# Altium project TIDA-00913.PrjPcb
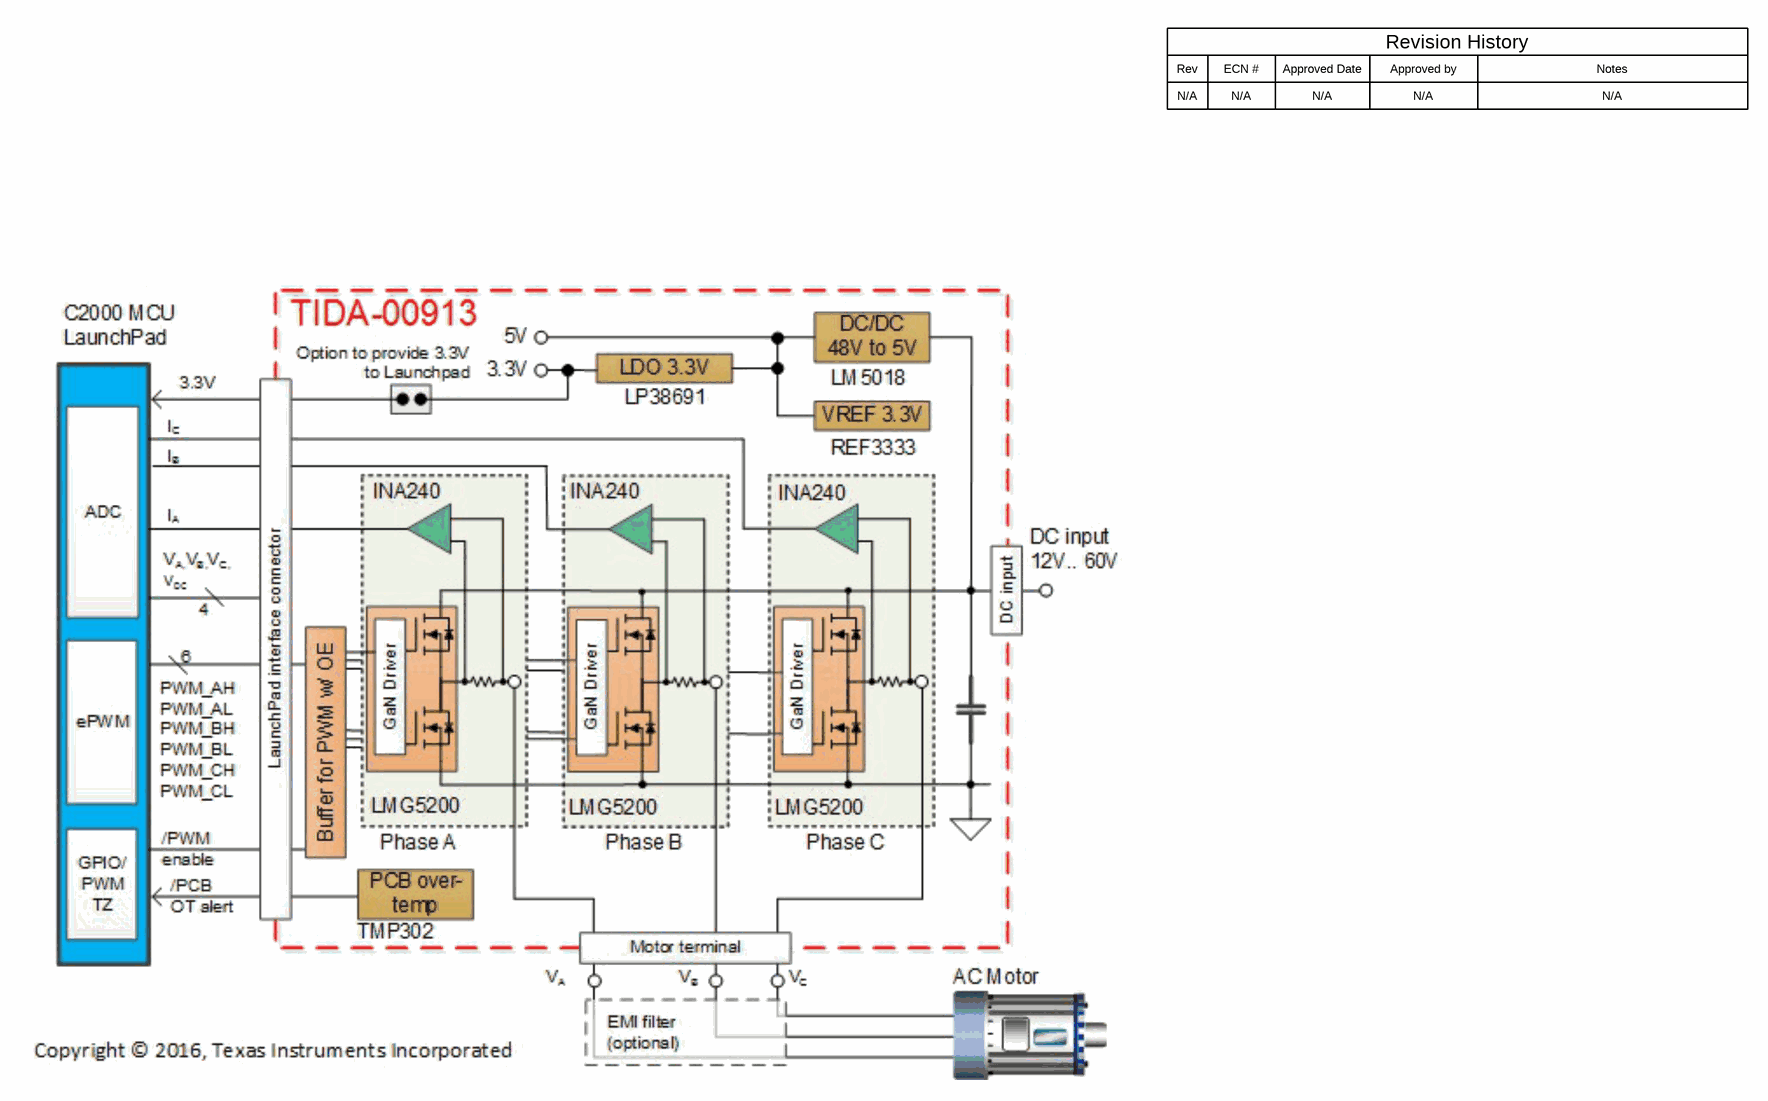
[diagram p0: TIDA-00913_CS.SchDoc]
TID: TIDA-00913; TechSupport: http://www.ti.com/support; SCH_Rev: E1; PRJ_Title: TI Design; PRJ_Number: TIDA-00913; PRJ_Engineer: Zhou/Staebler; PRJ_Customer: Public Release; PCB_Rev: E1; PCB_Layout: Zhou; CopyrightYear: 2016
6 sheets, 182 parts. Net scope: global (net labels, ports and power ports of the same name join across sheets).
Board file: TIDA-00913.PcbDoc
Sheets:
  TIDA-00913_CS.SchDoc
  TIDA-00913_GAN.SchDoc
  TIDA-00913_HW.SchDoc
  TIDA-00913_Interface.SchDoc
  TIDA-00913_PS.SchDoc
  TIDA-00913_Sensing.SchDoc

## Sheet TIDA-00913_CS.SchDoc
size 431 x 279 mm; Date: Not shown in title block; ApprovedBy: Not shown in title block; CheckedBy: Not shown in title block; Author: Not shown in title block; CompanyName: Not shown in title block; Engineer: Not shown in title block; Organization: Not shown in title block; Address1: Not shown in title block; Address2: Not shown in title block; Address3: Not shown in title block; Address4: Not shown in title block; DocumentNumber: 1; Revision: Use project parameter SCH_Rev; SheetNumber: 1; SheetTotal: 3; PageSetup: Record=PageOptions¦CenterHorizontal=True¦CenterVertical=True¦PrintScale=1.00¦XCorrection=1.00¦YCorrection=1.00¦PrintKind=0¦BorderSize=5000000¦LeftOffset=0¦BottomOffset=0¦Orientation=2¦PaperLength=1000¦PaperWidth=1000¦Scale=100¦PaperSource=15¦PrintQuality=600¦MediaType=1¦DitherType=10¦PaperKind=Letter¦PrintScaleMode=1

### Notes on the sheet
- Rev
- N/A
- ECN #
- Approved Date
- Approved by
- Revision History
- Notes

## Sheet TIDA-00913_GAN.SchDoc
size 431 x 279 mm; Date: Not shown in title block; ApprovedBy: Not shown in title block; CheckedBy: Not shown in title block; Author: Not shown in title block; CompanyName: Not shown in title block; Engineer: Not shown in title block; Organization: Not shown in title block; Address1: Not shown in title block; Address2: Not shown in title block; Address3: Not shown in title block; Address4: Not shown in title block; DocumentNumber: 1; Revision: Use project parameter SCH_Rev; SheetNumber: 2; SheetTotal: 3; PageSetup: Record=PageOptions¦CenterHorizontal=True¦CenterVertical=True¦PrintScale=1.00¦XCorrection=1.00¦YCorrection=1.00¦PrintKind=0¦BorderSize=5000000¦LeftOffset=0¦BottomOffset=0¦Orientation=2¦PaperLength=1000¦PaperWidth=1000¦Scale=100¦PaperSource=15¦PrintQuality=600¦MediaType=1¦DitherType=10¦PaperKind=Letter¦PrintScaleMode=1
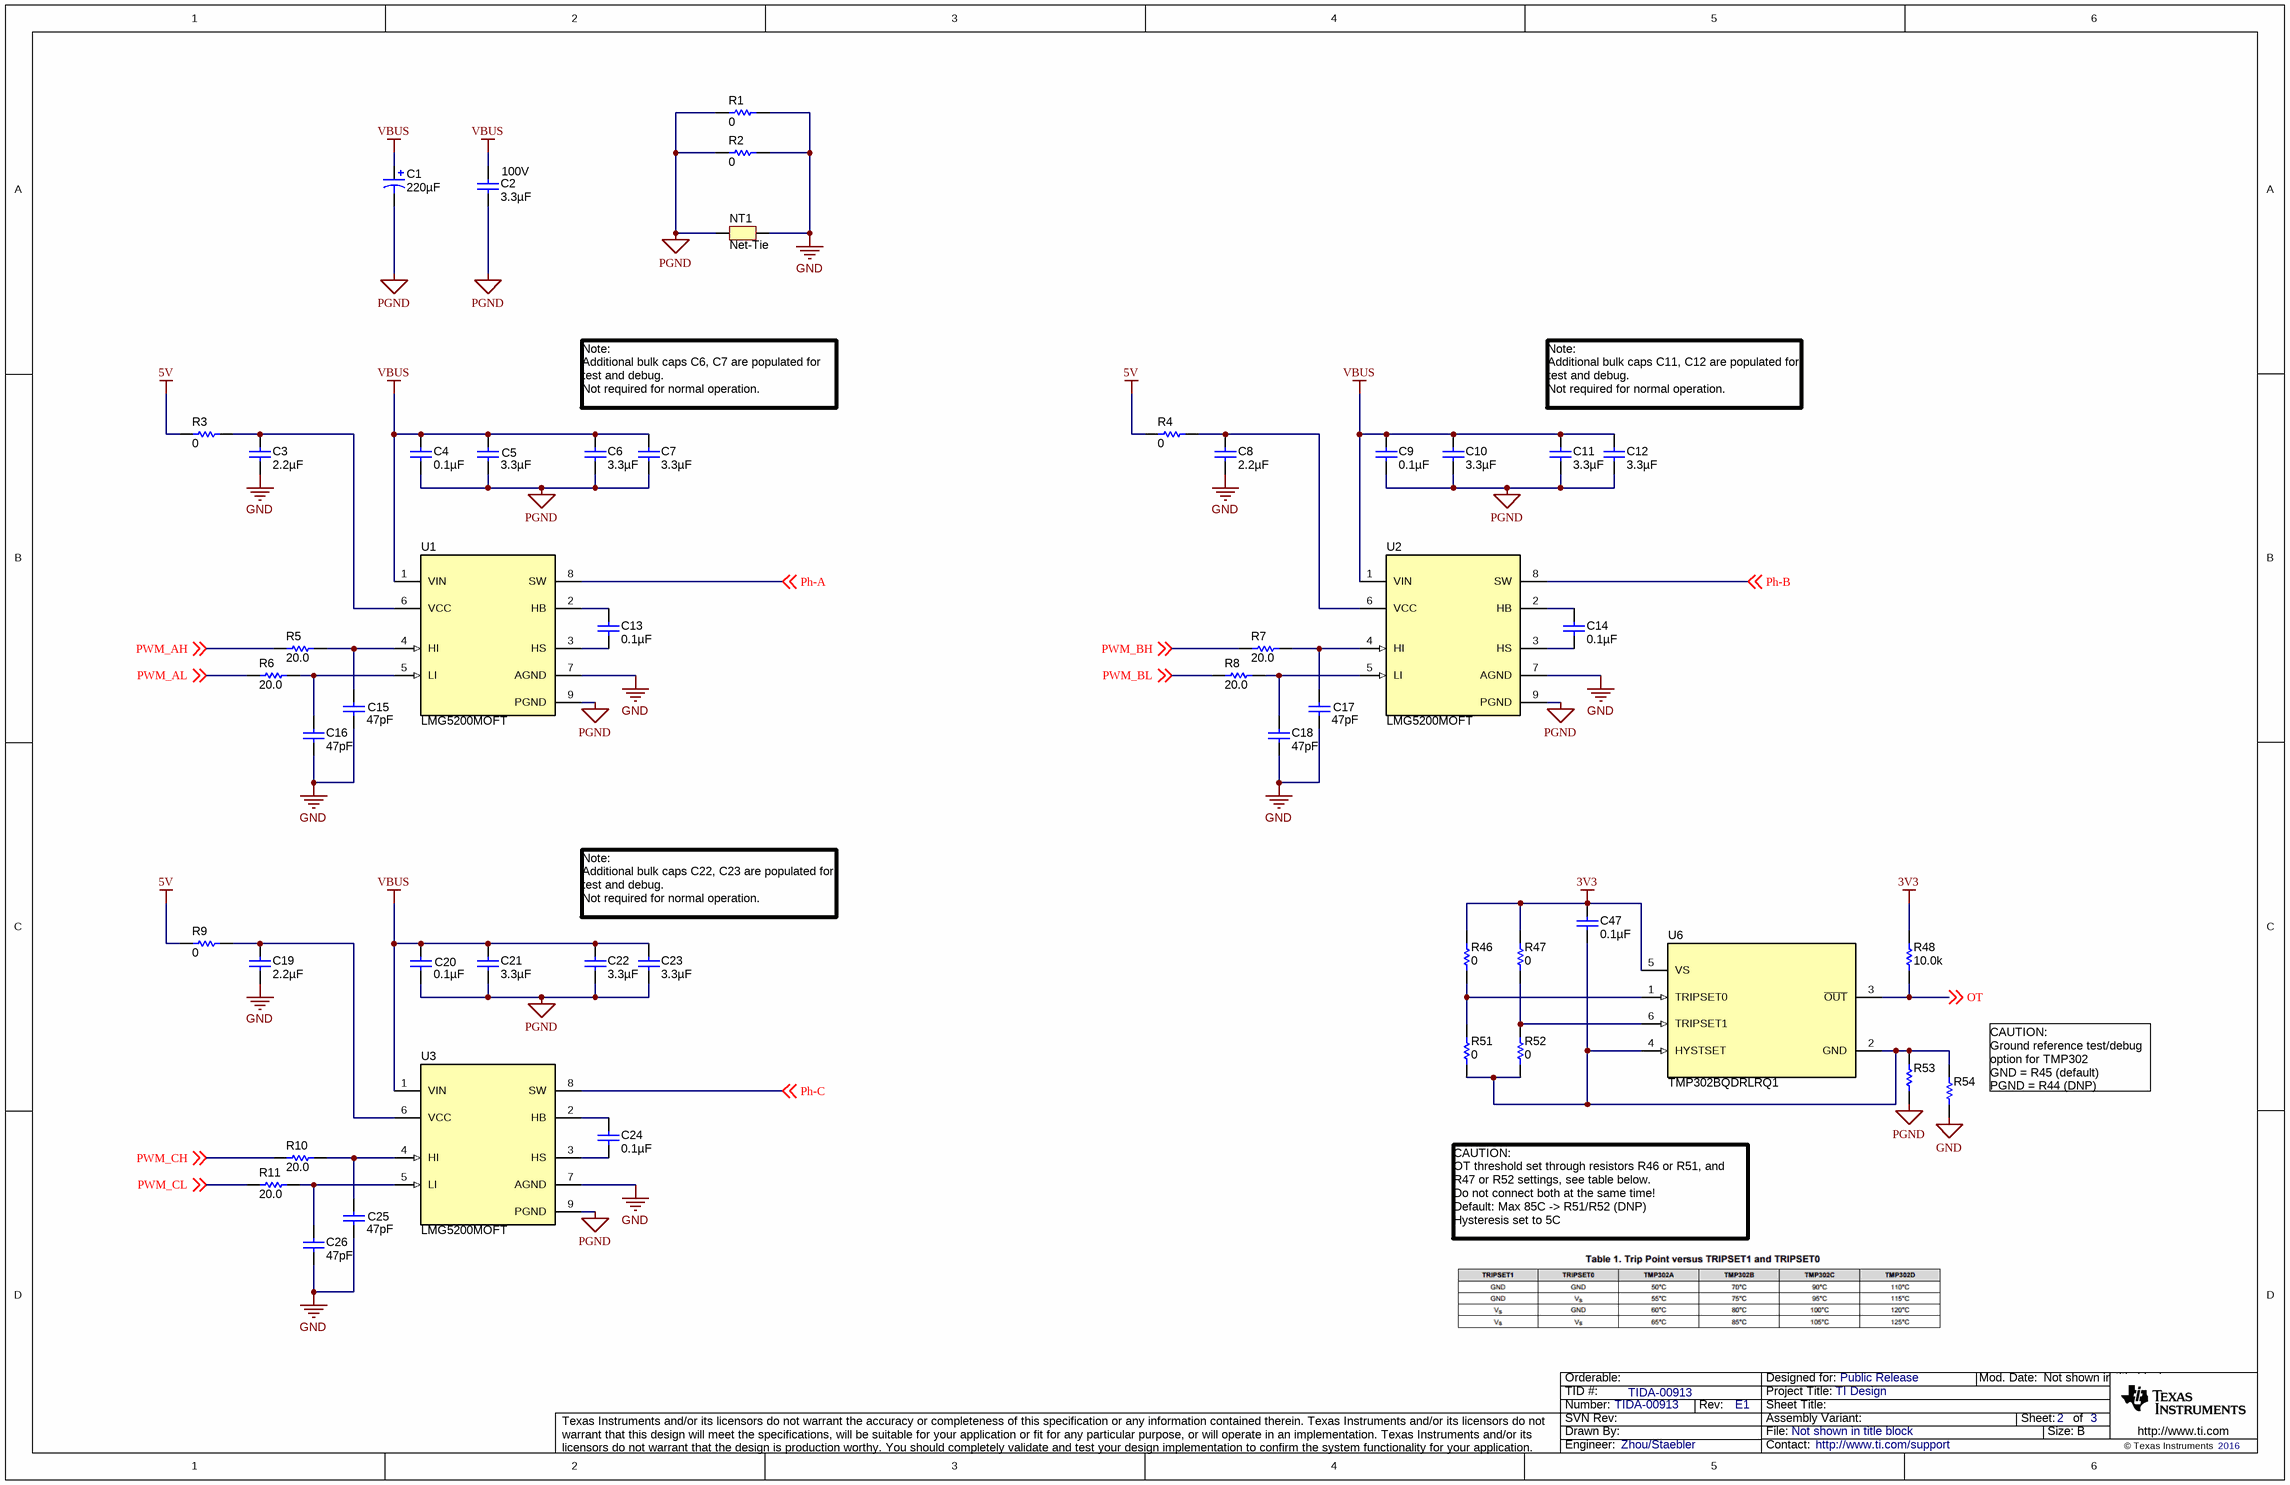
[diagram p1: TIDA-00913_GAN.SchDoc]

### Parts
C1  ValueDisplayed: 220µF  [KYB_1250x3500]  (hidden comment: EKYB101ELL221MK25S)
C2  ValueDisplayed: 3.3µF  Value2: 100V  [1206_190]  (hidden comment: C3216X7S2A335M160AB)
C3  ValueDisplayed: 2.2µF  [0402]  (hidden comment: C1005X5R1A225K050BC)
C4  ValueDisplayed: 0.1µF  [1206_190]  (hidden comment: C3216C0G2A104J160AC)
C5  ValueDisplayed: 3.3µF  [1206_190]  (hidden comment: C3216X7S2A335M160AB)
C6  ValueDisplayed: 3.3µF  [1206_190]  (hidden comment: C3216X7S2A335M160AB)
C7  ValueDisplayed: 3.3µF  [1206_190]  (hidden comment: C3216X7S2A335M160AB)
C8  ValueDisplayed: 2.2µF  [0402]  (hidden comment: C1005X5R1A225K050BC)
C9  ValueDisplayed: 0.1µF  [1206_190]  (hidden comment: C3216C0G2A104J160AC)
C10  ValueDisplayed: 3.3µF  [1206_190]  (hidden comment: C3216X7S2A335M160AB)
C11  ValueDisplayed: 3.3µF  [1206_190]  (hidden comment: C3216X7S2A335M160AB)
C12  ValueDisplayed: 3.3µF  [1206_190]  (hidden comment: C3216X7S2A335M160AB)
C13  ValueDisplayed: 0.1µF  [0402]  (hidden comment: GCM155R71C104KA55D)
C14  ValueDisplayed: 0.1µF  [0402]  (hidden comment: GCM155R71C104KA55D)
C15  ValueDisplayed: 47pF  [0402]  (hidden comment: GRM1555C1E470JA01D)
C16  ValueDisplayed: 47pF  [0402]  (hidden comment: GRM1555C1E470JA01D)
C17  ValueDisplayed: 47pF  [0402]  (hidden comment: GRM1555C1E470JA01D)
C18  ValueDisplayed: 47pF  [0402]  (hidden comment: GRM1555C1E470JA01D)
C19  ValueDisplayed: 2.2µF  [0402]  (hidden comment: C1005X5R1A225K050BC)
C20  ValueDisplayed: 0.1µF  [1206_190]  (hidden comment: C3216C0G2A104J160AC)
C21  ValueDisplayed: 3.3µF  [1206_190]  (hidden comment: C3216X7S2A335M160AB)
C22  ValueDisplayed: 3.3µF  [1206_190]  (hidden comment: C3216X7S2A335M160AB)
C23  ValueDisplayed: 3.3µF  [1206_190]  (hidden comment: C3216X7S2A335M160AB)
C24  ValueDisplayed: 0.1µF  [0402]  (hidden comment: GCM155R71C104KA55D)
C25  ValueDisplayed: 47pF  [0402]  (hidden comment: GRM1555C1E470JA01D)
C26  ValueDisplayed: 47pF  [0402]  (hidden comment: GRM1555C1E470JA01D)
C47  ValueDisplayed: 0.1µF  [0402]  (hidden comment: GCM155R71C104KA55D)
NT1  Net-Tie  [Net-Tie_50milWide_30milLong]  (net tie, no BOM)
R1  ValueDisplayed: 0  [0603]  (hidden comment: MCR03EZPJ000)
R2  ValueDisplayed: 0  [0603]  (hidden comment: MCR03EZPJ000)
R3  ValueDisplayed: 0  [0402]  (hidden comment: CRCW04020000Z0ED)
R4  ValueDisplayed: 0  [0402]  (hidden comment: CRCW04020000Z0ED)
R5  ValueDisplayed: 20.0  [0402]  (hidden comment: CRCW040220R0FKED)
R6  ValueDisplayed: 20.0  [0402]  (hidden comment: CRCW040220R0FKED)
R7  ValueDisplayed: 20.0  [0402]  (hidden comment: CRCW040220R0FKED)
R8  ValueDisplayed: 20.0  [0402]  (hidden comment: CRCW040220R0FKED)
R9  ValueDisplayed: 0  [0402]  (hidden comment: CRCW04020000Z0ED)
R10  ValueDisplayed: 20.0  [0402]  (hidden comment: CRCW040220R0FKED)
R11  ValueDisplayed: 20.0  [0402]  (hidden comment: CRCW040220R0FKED)
R46  ValueDisplayed: 0  [0402]  (hidden comment: CRCW04020000Z0ED)
R47  ValueDisplayed: 0  [0402]  (hidden comment: CRCW04020000Z0ED)
R48  ValueDisplayed: 10.0k  [0402]  (hidden comment: CRCW040210K0FKED)
R51  ValueDisplayed: 0  [0402]  (hidden comment: CRCW04020000Z0ED)
R52  ValueDisplayed: 0  [0402]  (hidden comment: CRCW04020000Z0ED)
R53  MCR03EZPJ000  [0603]  (value not drawn)
R54  MCR03EZPJ000  [0603]  (value not drawn)
U1  LMG5200MOFT  [MOF0009A]
U2  LMG5200MOFT  [MOF0009A]
U3  LMG5200MOFT  [MOF0009A]
U6  TMP302BQDRLRQ1  [DRL0006A]

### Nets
3V3: C47.1 R46.2 R47.2 R48.2 U6.5(VS)
5V: R3.2 R4.2 R9.2
GND: C3.2 C8.2 C15.2 C16.2 C17.2 C18.2 C19.2 C25.2 C26.2 NT1.2 R1.2 R2.2 R54.1 U1.7(AGND) U2.7(AGND) U3.7(AGND)
PGND: C1.2(-) C2.2 C4.2 C5.2 C6.2 C7.2 C9.1 C10.2 C11.2 C12.2 C20.1 C21.2 C22.2 C23.2 NT1.1 R1.1 R2.1 R53.1 U1.9(PGND) U2.9(PGND) U3.9(PGND)
VBUS: C1.1(+) C2.1 C4.1 C5.1 C6.1 C7.1 C9.2 C10.1 C11.1 C12.1 C20.2 C21.1 C22.1 C23.1 U1.1(VIN) U2.1(VIN) U3.1(VIN)
OT: R48.1 U6.3(~{OUT}) ; off-sheet OT
Ph-A: U1.8(SW) ; off-sheet Ph-A
Ph-B: U2.8(SW) ; off-sheet Ph-B
Ph-C: U3.8(SW) ; off-sheet Ph-C
PWM_AH: R5.2 ; off-sheet PWM_AH
PWM_AL: R6.2 ; off-sheet PWM_AL
PWM_BH: R7.2 ; off-sheet PWM_BH
PWM_BL: R8.2 ; off-sheet PWM_BL
PWM_CH: R10.2 ; off-sheet PWM_CH
PWM_CL: R11.2 ; off-sheet PWM_CL
NetC3_1: C3.1 R3.1 U1.6(VCC)
NetC8_1: C8.1 R4.1 U2.6(VCC)
NetC13_1: C13.1 U1.2(HB)
NetC13_2: C13.2 U1.3(HS)
NetC14_1: C14.1 U2.2(HB)
NetC14_2: C14.2 U2.3(HS)
NetC15_1: C15.1 R5.1 U1.4(HI)
NetC16_1: C16.1 R6.1 U1.5(LI)
NetC17_1: C17.1 R7.1 U2.4(HI)
NetC18_1: C18.1 R8.1 U2.5(LI)
NetC19_1: C19.1 R9.1 U3.6(VCC)
NetC24_1: C24.1 U3.2(HB)
NetC24_2: C24.2 U3.3(HS)
NetC25_1: C25.1 R10.1 U3.4(HI)
NetC26_1: C26.1 R11.1 U3.5(LI)
NetC47_2: C47.2 R51.1 R52.1 R53.2 R54.2 U6.2(GND) U6.4(HYSTSET)
NetR46_1: R46.1 R51.2 U6.1(TRIPSET0)
NetR47_1: R47.1 R52.2 U6.6(TRIPSET1)

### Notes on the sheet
- Note:
  Additional bulk caps C6, C7 are populated for test and debug.
  Not required for normal operation.
- Note:
  Additional bulk caps C11, C12 are populated for test and debug.
  Not required for normal operation.
- Note:
  Additional bulk caps C22, C23 are populated for test and debug.
  Not required for normal operation.
- (near R54) CAUTION:
  Ground reference test/debug option for TMP302
  GND = R45 (default)
  PGND = R44 (DNP)
- CAUTION:
  OT threshold set through resistors R46 or R51, and R47 or R52 settings, see table below.
  Do not connect both at the same time!
  Default: Max 85C -> R51/R52 (DNP)
  Hysteresis set to 5C

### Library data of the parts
C1 = EKYB101ELL391MK35S: CAP, AL, 220 µF, 100 V, +/- 20%, 0.039 ohm, TH; Manufacturer: Chemi-Con; Polarized: Y; CompType: Capacitor; Value: 220uF; U/M: EA; Cap_F: 0.00022; Tolerance_%: 20; VDC_V: 100; Value2: 100V; ESR_ohm: 0.039; IRMS_A: 2.25; TaMin_C: -40; TaMax_C: 105; Cap_Case: 12.5x25mm; AEC Category: Q200; AEC Qualified: N
C2 = C3216X7S2A335M160AB: CAP, CERM, 3.3 µF, 100 V, +/- 20%, X7S, 1206_190; Manufacturer: TDK; Polarized: N; CompType: Capacitor; Value: 3.3uF; U/M: EA; Cap_F: 0.0000033; Tolerance_%: 20; Value1: Unknown; VDC_V: 100; TaMin_C: -55; TaMax_C: 125; Cap_Case: 1206; AEC Category: Q200
C3 C8 C19 = C1005X5R1A225K050BC: CAP, CERM, 2.2 µF, 10 V, +/- 10%, X5R, 0402; Manufacturer: TDK; Polarized: N; CompType: Capacitor; Value: 2.2uF; U/M: EA; Cap_F: 0.0000022; Tolerance_%: 10; Value1: Unknown; Value2: 10V; TaMin_C: -55; TaMax_C: 85; SizeArea_mm2: 0.5; SizeAreaWB_mm2: 3; SizeX_mm: 1; SizeZ_mm: 0.6; AEC Category: Q200
C4 C9 C20 = C3216C0G2A104J160AC: CAP, CERM, 0.1 µF, 100 V, +/- 5%, C0G/NP0, 1206_190; Manufacturer: TDK; Polarized: N; CompType: Capacitor; Value: 0.1uF; U/M: EA; Cap_F: 0.0000001; Tolerance_%: 5; Value1: Unknown; VDC_V: 100; Value2: 100V; TaMin_C: -55; TaMax_C: 125; Cap_Case: 1206; SizeArea_mm2: 5.12; SizeAreaWB_mm2: 10.92; SizeX_mm: 3.2; SizeY_mm: 1.6; SizeZ_mm: 1.9; AEC Category: Q200
C5-C7 C10-C12 C21-C23 = C3216X7S2A335M160AB: CAP, CERM, 3.3 µF, 100 V, +/- 20%, X7S, 1206_190; Manufacturer: TDK; Polarized: N; CompType: Capacitor; Value: 3.3uF; U/M: EA; Cap_F: 0.0000033; Tolerance_%: 20; ESR_ohm: 0.003048; Value1: 0.003048 ohm; VDC_V: 100; Value2: 100V; IRMS_A: 4.15703; TaMin_C: -55; TaMax_C: 125; AEC Category: Q200; SizeArea_mm2: 5.12; SizeAreaWB_mm2: 10.92; SizeX_mm: 3.2; SizeY_mm: 1.6; SizeZ_mm: 1.9
C13 C14 C24 C47 = GCM155R71C104KA55D: CAP, CERM, 0.1 µF, 16 V, +/- 10%, X7R, 0402; Manufacturer: MuRata; Polarized: N; CompType: Capacitor; Value: 0.1uF; U/M: EA; Cap_F: 0.0000001; Tolerance_%: 10; Value1: Unknown; VDC_V: 16; Value2: 16V; TaMin_C: -55; TaMax_C: 125; AEC Category: Q200
C15-C18 C25 C26 = GRM1555C1E470JA01D: CAP, CERM, 47 pF, 25 V, +/- 5%, C0G/NP0, 0402; Manufacturer: MuRata; Polarized: N; CompType: Capacitor; Value: 47pF; U/M: EA; Cap_F: 0.000000000047; Tolerance_%: 5; Value1: Unknown; VDC_V: 25; Value2: 25V; TaMin_C: -55; TaMax_C: 125; AEC Category: Q200
NT1 = Net-Tie: Single point connection between nets.; SymbolCreator: codlsc
R1 R2 R53 R54 = MCR03EZPJ000: RES, 0, 5%, 0.1 W, 0603; Manufacturer: Rohm; CompType: Resistor; Value: 0; Value_Code: 0000; Tolerance_%: 5; Power_W: 0.1; Value2: 0.1W; TempCo: ppm/C; SizeArea_mm2: 1.28; SizeX_mm: 1.6; SizeY_mm: 0.8; SizeZ_mm: 1; EIA_Code: E24; U/M: EA; AEC Category: Q200; AEC Qualified: N
R3 R4 R9 R46 R47 R51 R52 = CRCW04020000Z0ED: RES, 0, 5%, 0.063 W, 0402; Manufacturer: Vishay-Dale; CompType: Resistor; Value: 0; Value_Code: 0000; Tolerance_%: 5; Power_W: 0.063; Value2: 0.063W; VDC_V: 50; TempCo: 200 ppm/C; SizeArea_mm2: 0.5; SizeX_mm: 1; SizeZ_mm: 0.6; EIA_Code: E24; U/M: EA; AEC Category: Q200
R5-R8 R10 R11 = CRCW040220R0FKED: RES, 20.0, 1%, 0.063 W, 0402; Manufacturer: Vishay-Dale; CompType: Resistor; Value: 20.0; Res_ohm: 20; Value_Code: 20R0; Tolerance_%: 1; Power_W: 0.063; Value2: 0.063W; VDC_V: 50; TempCo: 100 ppm/C; EIA_Code: E96; U/M: EA; AEC Category: Q200
R48 = CRCW040210K0FKED: RES, 10.0 k, 1%, 0.063 W, 0402; Manufacturer: Vishay-Dale; CompType: Resistor; Value: 10.0k; Res_ohm: 10000; Value_Code: 10k0; Tolerance_%: 1; Power_W: 0.063; Value2: 0.063W; VDC_V: 50; TempCo: 100 ppm/C; EIA_Code: E96; U/M: EA; AEC Category: Q200; SizeArea_mm2: 0.5; SizeZ_mm: 0.6
U1-U3 = PLMG5200MOFT: 100V GaN Half Bridge Power Module, MOF0009A; Manufacturer: Texas Instruments; SymbolCreator: Altium; CompType: IC; U/M: EA
U6 = TMP302BQDRLRQ1: Automotive Grade, Low-Power, Easy-to-Use, Temperature Switch in MicroPackage, DRL0006A; Manufacturer: Texas Instruments; SymbolCreator: Altium; SizeArea_mm2: 2.56; SizeAreaWB_mm2: 6.76; SizeX_mm: 1.6; SizeZ_mm: 0.6; CompType: IC; U/M: EA

## Sheet TIDA-00913_HW.SchDoc
size 431 x 279 mm; Date: Not shown in title block; ApprovedBy: Not shown in title block; CheckedBy: Not shown in title block; Author: Not shown in title block; CompanyName: Not shown in title block; Engineer: Not shown in title block; Organization: Not shown in title block; Address1: Not shown in title block; Address2: Not shown in title block; Address3: Not shown in title block; Address4: Not shown in title block; DocumentNumber: 1; Revision: Use project parameter SCH_Rev; SheetNumber: 3; SheetTotal: 3; PageSetup: Record=PageOptions¦CenterHorizontal=True¦CenterVertical=True¦PrintScale=1.00¦XCorrection=1.00¦YCorrection=1.00¦PrintKind=0¦BorderSize=5000000¦LeftOffset=0¦BottomOffset=0¦Orientation=2¦PaperLength=1000¦PaperWidth=1000¦Scale=100¦PaperSource=15¦PrintQuality=600¦MediaType=1¦DitherType=10¦PaperKind=Letter¦PrintScaleMode=1
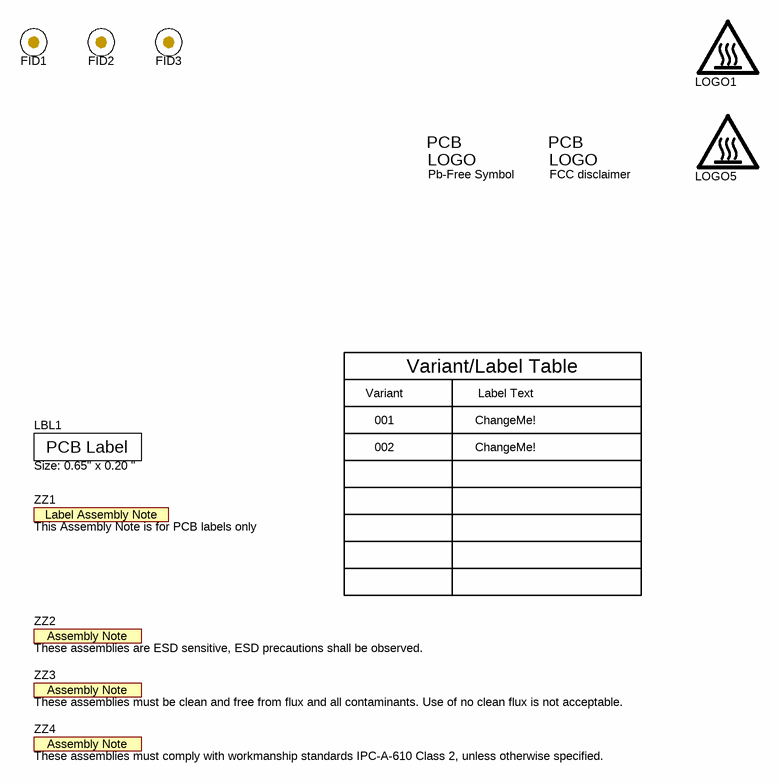
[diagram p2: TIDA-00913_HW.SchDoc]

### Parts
FID1  Fiducial  [Fiducial10-20]  (value not drawn)
FID2  Fiducial  [Fiducial10-20]  (value not drawn)
FID3  Fiducial  [Fiducial10-20]  (value not drawn)
LBL1  Size: 0.65" x 0.20 "  [Label_650x200]
LOGO1  CAUTION HOT SURFACE  [IEC_HotSurface_Small]  (value not drawn)  (no BOM)
Logo3  Pb-Free Symbol  [Pb-Free_Overlay_Small]  (no BOM)
Logo4  FCC disclaimer  [FCC_disclaimer]  (no BOM)
LOGO5  CAUTION HOT SURFACE  [IEC_HotSurface_Small]  (value not drawn)  (no BOM)
ZZ1  This Assembly Note is for PCB labels only  [AssemblyNoteLabel]  (no BOM)
ZZ2  These assemblies are ESD sensitive, ESD precautions shall be observed.  [AssemblyNote]  (no BOM)
ZZ3  These assemblies must be clean and free from flux and all contaminants. Use of no clean flux is not acceptable.  [AssemblyNote]  (no BOM)
ZZ4  These assemblies must comply with workmanship standards IPC-A-610 Class 2, unless otherwise specified.  [AssemblyNote]  (no BOM)

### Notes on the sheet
- Variant
- Variant/Label Table
- Label Text
- 001
- 002
- ChangeMe!

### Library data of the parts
FID1-FID3 = Fiducial: Fiducial mark.  There is nothing to buy or mount.; SymbolCreator: codlsc
LBL1 = THT-14-423-10: Thermal Transfer Printable Labels, 0.650" W x 0.200" H - 10,000 per roll; Manufacturer: Brady; SymbolCreator: a0412235; CompType: Label
LOGO1 LOGO5 = IEC_HotSurface: IEC 61010-1 Hot Surface Warning; SymbolCreator: a0412235
Logo3 = Pb-Free: SymbolCreator: a0412235
Logo4 = FCC_disclaimer: SymbolCreator: codlsc
ZZ1 = AssemblyNoteLabel: SymbolCreator: a0412235
ZZ2-ZZ4 = AssemblyNote: SymbolCreator: codlsc

## Sheet TIDA-00913_Interface.SchDoc
size 431 x 279 mm; Date: Not shown in title block; ApprovedBy: Not shown in title block; CheckedBy: Not shown in title block; Author: Not shown in title block; CompanyName: Not shown in title block; Engineer: Not shown in title block; Organization: Not shown in title block; Address1: Not shown in title block; Address2: Not shown in title block; Address3: Not shown in title block; Address4: Not shown in title block; DocumentNumber: 1; Revision: Use project parameter SCH_Rev; SheetNumber: 3; SheetTotal: 3; PageSetup: Record=PageOptions¦CenterHorizontal=True¦CenterVertical=True¦PrintScale=1.00¦XCorrection=1.00¦YCorrection=1.00¦PrintKind=0¦BorderSize=5000000¦LeftOffset=0¦BottomOffset=0¦Orientation=2¦PaperLength=1000¦PaperWidth=1000¦Scale=100¦PaperSource=15¦PrintQuality=600¦MediaType=1¦DitherType=10¦PaperKind=Letter¦PrintScaleMode=1
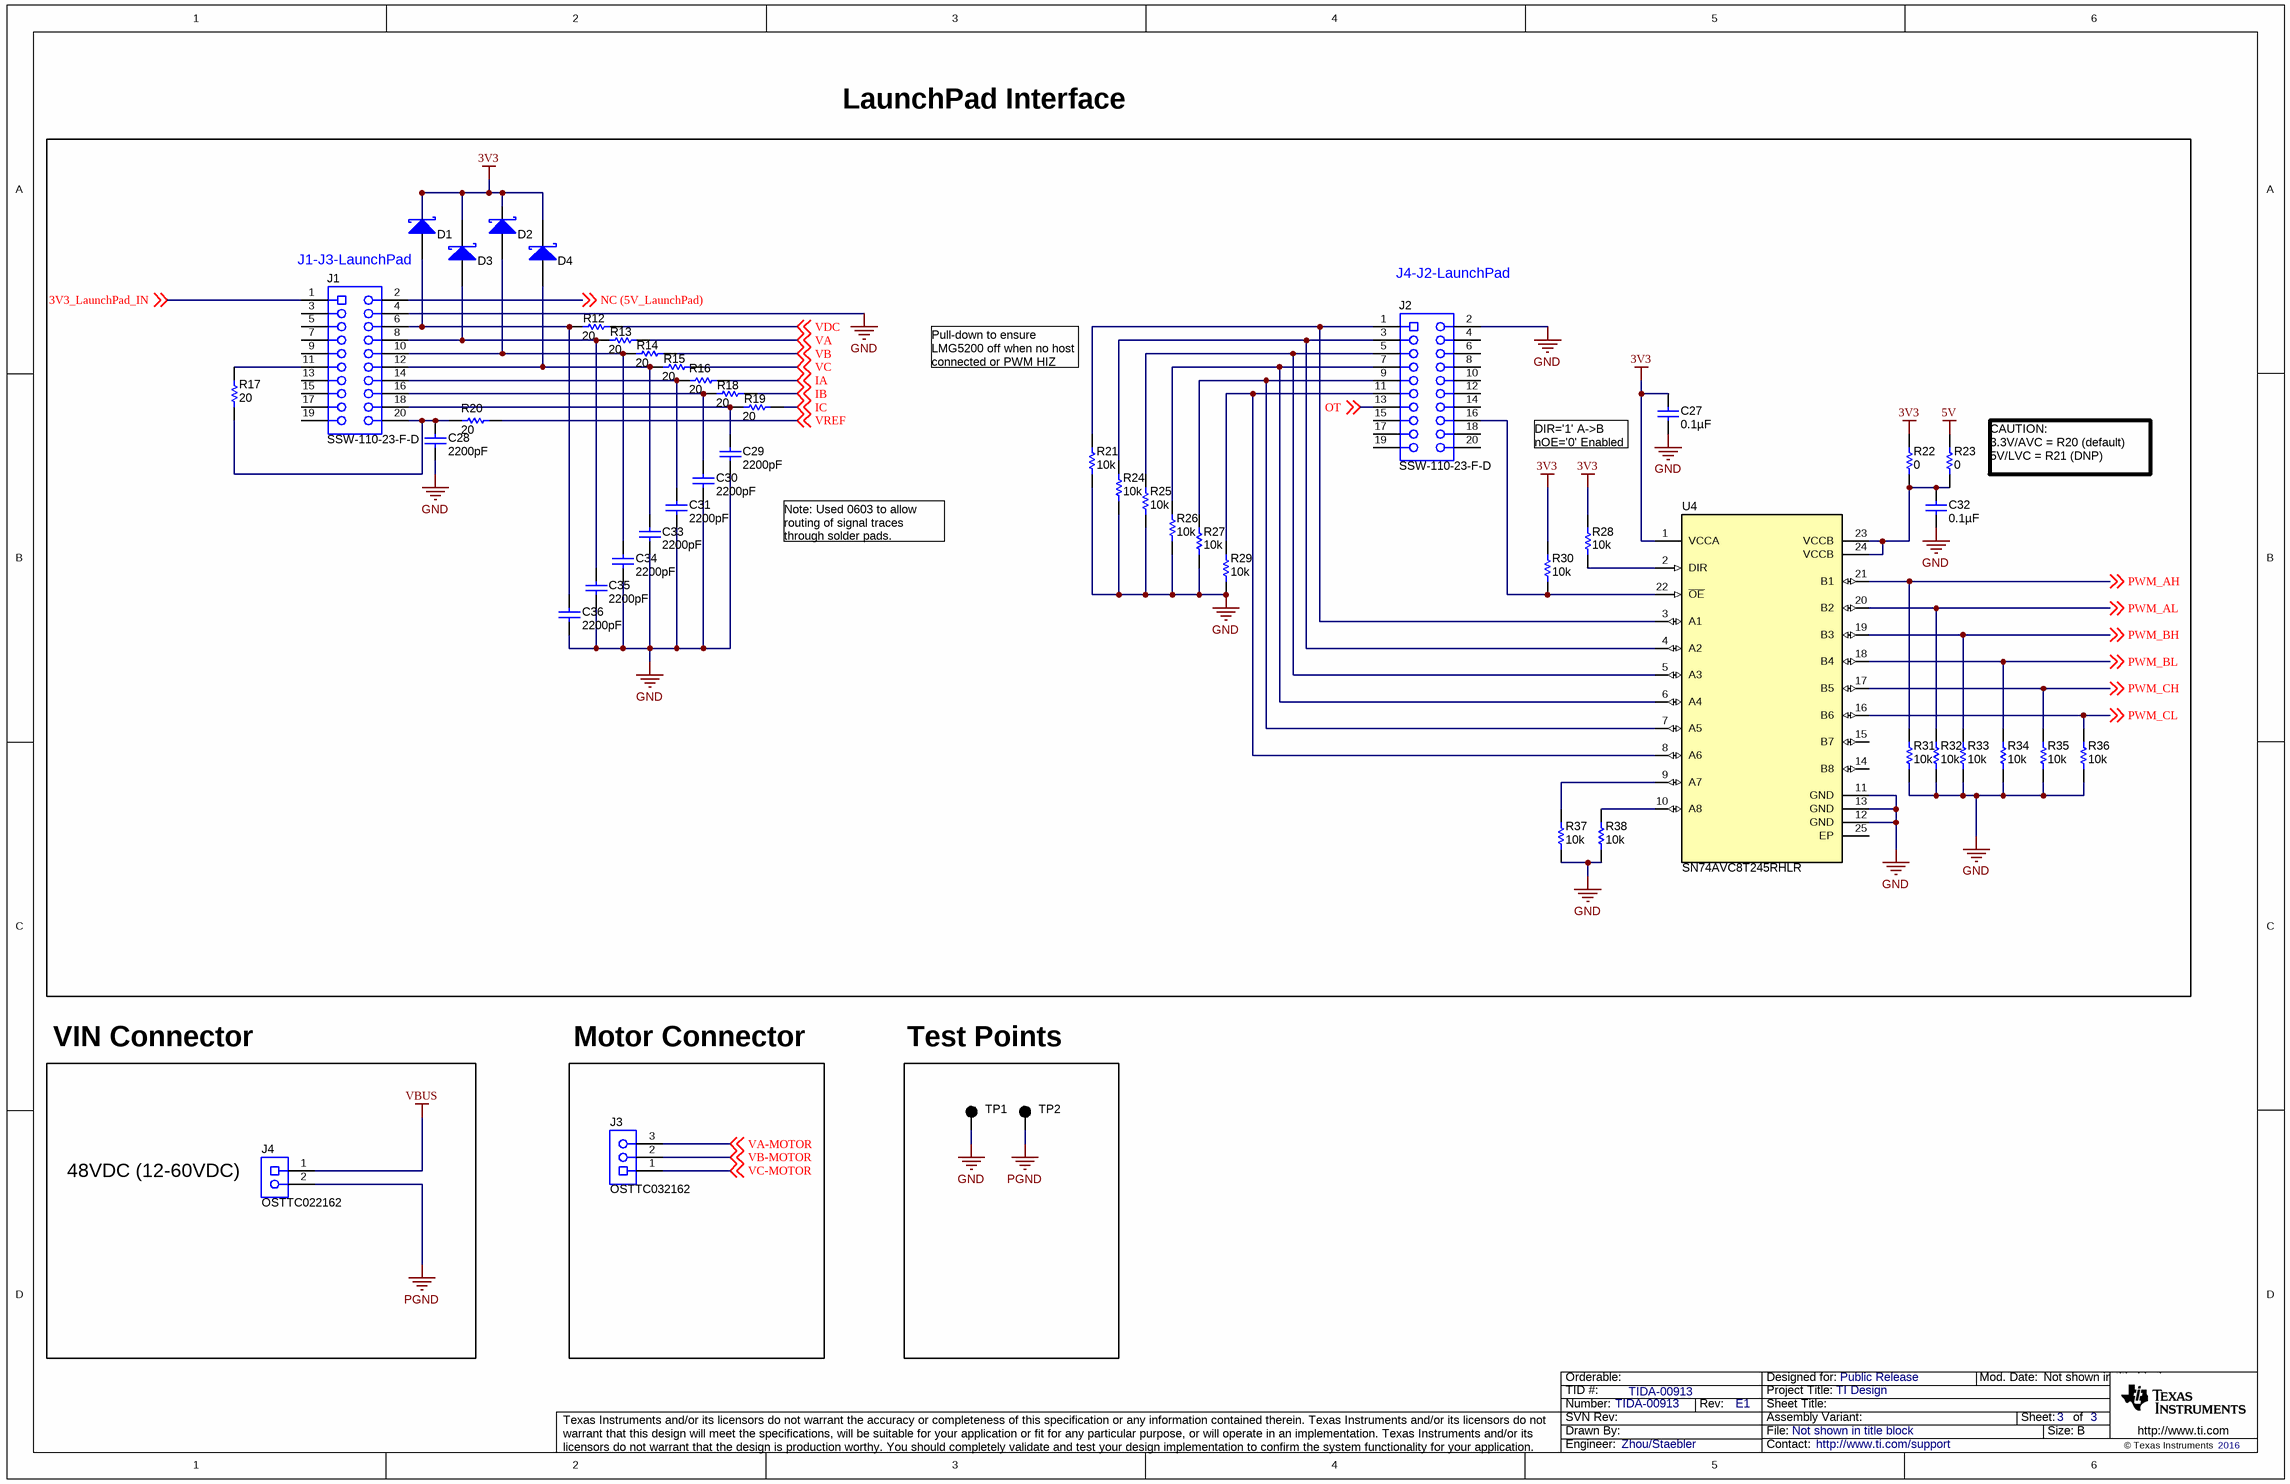
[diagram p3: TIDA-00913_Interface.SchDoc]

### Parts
C27  ValueDisplayed: 0.1µF  [0402]  (hidden comment: GRM155R71A104KA01D)
C28  ValueDisplayed: 2200pF  [0603]  (hidden comment: 885012206036)
C29  ValueDisplayed: 2200pF  [0603]  (hidden comment: 885012206036)
C30  ValueDisplayed: 2200pF  [0603]  (hidden comment: 885012206036)
C31  ValueDisplayed: 2200pF  [0603]  (hidden comment: 885012206036)
C32  ValueDisplayed: 0.1µF  [0402]  (hidden comment: GRM155R71A104KA01D)
C33  ValueDisplayed: 2200pF  [0603S]  (hidden comment: 885012206036)
C34  ValueDisplayed: 2200pF  [0603]  (hidden comment: 885012206036)
C35  ValueDisplayed: 2200pF  [0603]  (hidden comment: 885012206036)
C36  ValueDisplayed: 2200pF  [0603]  (hidden comment: 885012206036)
D1  1PS79SB70,115  [SOD-523]  (value not drawn)
D2  1PS79SB70,115  [SOD-523]  (value not drawn)
D3  1PS79SB70,115  [SOD-523]  (value not drawn)
D4  1PS79SB70,115  [SOD-523]  (value not drawn)
J1  SSW-110-23-F-D  [CONN_SSW-110-23-F-D]
J2  SSW-110-23-F-D  [CONN_SSW-110-23-F-D]
J3  OSTTC032162  [On-Shore_OSTTC032162]
J4  OSTTC022162  [On-Shore_OSTTC022162]
R12  ValueDisplayed: 20  [0402]  (hidden comment: CRCW040220R0JNED)
R13  ValueDisplayed: 20  [0402]  (hidden comment: CRCW040220R0JNED)
R14  ValueDisplayed: 20  [0402]  (hidden comment: CRCW040220R0JNED)
R15  ValueDisplayed: 20  [0402]  (hidden comment: CRCW040220R0JNED)
R16  ValueDisplayed: 20  [0402]  (hidden comment: CRCW040220R0JNED)
R17  ValueDisplayed: 20  [0402]  (hidden comment: CRCW040220R0JNED)
R18  ValueDisplayed: 20  [0402]  (hidden comment: CRCW040220R0JNED)
R19  ValueDisplayed: 20  [0402]  (hidden comment: CRCW040220R0JNED)
R20  ValueDisplayed: 20  [0402]  (hidden comment: CRCW040220R0JNED)
R21  ValueDisplayed: 10k  [0402]  (hidden comment: CRCW040210K0JNED)
R22  ValueDisplayed: 0  [0402]  (hidden comment: CRCW04020000Z0ED)
R23  ValueDisplayed: 0  [0402]  (hidden comment: CRCW04020000Z0ED)
R24  ValueDisplayed: 10k  [0402]  (hidden comment: CRCW040210K0JNED)
R25  ValueDisplayed: 10k  [0402]  (hidden comment: CRCW040210K0JNED)
R26  ValueDisplayed: 10k  [0402]  (hidden comment: CRCW040210K0JNED)
R27  ValueDisplayed: 10k  [0402]  (hidden comment: CRCW040210K0JNED)
R28  ValueDisplayed: 10k  [0402]  (hidden comment: CRCW040210K0JNED)
R29  ValueDisplayed: 10k  [0402]  (hidden comment: CRCW040210K0JNED)
R30  ValueDisplayed: 10k  [0402]  (hidden comment: CRCW040210K0JNED)
R31  ValueDisplayed: 10k  [0402]  (hidden comment: CRCW040210K0JNED)
R32  ValueDisplayed: 10k  [0402]  (hidden comment: CRCW040210K0JNED)
R33  ValueDisplayed: 10k  [0402]  (hidden comment: CRCW040210K0JNED)
R34  ValueDisplayed: 10k  [0402]  (hidden comment: CRCW040210K0JNED)
R35  ValueDisplayed: 10k  [0402]  (hidden comment: CRCW040210K0JNED)
R36  ValueDisplayed: 10k  [0402]  (hidden comment: CRCW040210K0JNED)
R37  ValueDisplayed: 10k  [0402]  (hidden comment: CRCW040210K0JNED)
R38  ValueDisplayed: 10k  [0402]  (hidden comment: CRCW040210K0JNED)
TP1  5001  [Keystone5001]  (value not drawn)
TP2  5001  [Keystone5001]  (value not drawn)
U4  SN74AVC8T245RHLR  [RHL0024A]

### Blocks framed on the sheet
48VDC (12-60VDC): J4

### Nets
3V3: C27.1 D1.1(K) D2.1(K) D3.1(K) D4.1(K) R22.2 R28.1 R30.2 U4.1(VCCA)
5V: R23.2
GND: C27.2 C28.2 C29.2 C30.2 C31.2 C32.2 C33.2 C34.2 C35.2 C36.2 J1.4 J2.2 R21.1 R24.1 R25.1 R26.1 R27.1 R29.1 R31.1 R32.1 R33.1 R34.1 R35.1 R36.1 R37.1 R38.1 TP1.1 U4.11(GND) U4.12(GND) U4.13(GND)
PGND: J4.2 TP2.1
VBUS: J4.1
3V3_LaunchPad_IN: J1.1 ; off-sheet 3V3_LaunchPad_IN
IA: R16.1 ; off-sheet IA
IB: R18.1 ; off-sheet IB
IC: R19.1 ; off-sheet IC
NC (5V_LaunchPad): J1.2 ; off-sheet NC (5V_LaunchPad)
OT: J2.13 ; off-sheet OT
PWM_AH: R31.2 U4.21(B1) ; off-sheet PWM_AH
PWM_AL: R32.2 U4.20(B2) ; off-sheet PWM_AL
PWM_BH: R33.2 U4.19(B3) ; off-sheet PWM_BH
PWM_BL: R34.2 U4.18(B4) ; off-sheet PWM_BL
PWM_CH: R35.2 U4.17(B5) ; off-sheet PWM_CH
PWM_CL: R36.2 U4.16(B6) ; off-sheet PWM_CL
VA: R13.1 ; off-sheet VA
VA-MOTOR: J3.3 ; off-sheet VA-MOTOR
VB: R14.1 ; off-sheet VB
VB-MOTOR: J3.2 ; off-sheet VB-MOTOR
VC: R15.1 ; off-sheet VC
VC-MOTOR: J3.1 ; off-sheet VC-MOTOR
VDC: R12.1 ; off-sheet VDC
VREF: R20.1 ; off-sheet VREF
NetC28_1: C28.1 J1.20 R17.2 R20.2
NetC29_1: C29.1 J1.18 R19.2
NetC30_1: C30.1 J1.16 R18.2
NetC31_1: C31.1 J1.14 R16.2
NetC32_1: C32.1 R22.1 R23.1 U4.23(VCCB) U4.24(VCCB)
NetC33_1: C33.1 D4.2(A) J1.12 R15.2
NetC34_1: C34.1 D2.2(A) J1.10 R14.2
NetC35_1: C35.1 D3.2(A) J1.8 R13.2
NetC36_1: C36.1 D1.2(A) J1.6 R12.2
NetJ1_11: J1.11 R17.1
NetJ2_1: J2.1 R21.2 U4.3(A1)
NetJ2_3: J2.3 R24.2 U4.4(A2)
NetJ2_5: J2.5 R25.2 U4.5(A3)
NetJ2_7: J2.7 R26.2 U4.6(A4)
NetJ2_9: J2.9 R27.2 U4.7(A5)
NetJ2_11: J2.11 R29.2 U4.8(A6)
NetJ2_16: J2.16 R30.1 U4.22(~{OE})
NetR28_2: R28.2 U4.2(DIR)
NetR37_2: R37.2 U4.9(A7)
NetR38_2: R38.2 U4.10(A8)

Not connected (* = marked no-connect by the designer): J1 3 5 7 9 13 15 17 19; J2 4 6 8 10 12 14 15 17 18 19 20; U4 14(B8) 15(B7) 25(EP)

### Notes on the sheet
- LaunchPad Interface
- J1-J3-LaunchPad
- (near J2) J4-J2-LaunchPad
- Pull-down to ensure LMG5200 off when no host connected or PWM HIZ
- (near C27) DIR='1' A->B
  nOE='0' Enabled
- CAUTION:
  3.3V/AVC = R20 (default)
  5V/LVC = R21 (DNP)
- Note: Used 0603 to allow routing of signal traces through solder pads.
- VIN Connector
- Motor Connector
- Test Points

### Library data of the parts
C27 C32 = GRM155R71A104KA01D: CAP, CERM, 0.1 µF, 10 V, +/- 10%, X7R, 0402; Manufacturer: MuRata; Polarized: N; CompType: Capacitor; Value: 0.1uF; U/M: EA; Cap_F: 0.0000001; Tolerance_%: 10; Value1: Unknown; Value2: 10V; TaMin_C: -55; TaMax_C: 125; SizeArea_mm2: 0.5; SizeAreaWB_mm2: 3; SizeX_mm: 1; SizeZ_mm: 0.6; AEC Category: Q200
C28-C31 C34-C36 = 885012206036: CAP, CERM, 2200 pF, 16 V, +/- 10%, X7R, 0603; Manufacturer: Wurth Elektronik; Polarized: N; CompType: Capacitor; Value: 2200pF; U/M: EA; Cap_F: 0.0000000022; Tolerance_%: 10; Value1: Unknown; VDC_V: 16; Value2: 16V; TaMin_C: -55; TaMax_C: 125; AEC Category: Q200; SizeArea_mm2: 1.28; SizeAreaWB_mm2: 4.68; SizeX_mm: 1.6; SizeY_mm: 0.8; SizeZ_mm: 1
C33 = 885012206036: CAP, CERM, 2200 pF, 16 V, +/- 10%, X7R, 0603; Manufacturer: Wurth Elektronik; Polarized: N; CompType: Capacitor; Value: 2200pF; U/M: EA; Cap_F: 0.0000000022; Tolerance_%: 10; Value1: Unknown; VDC_V: 16; Value2: 16V; TaMin_C: -55; TaMax_C: 125; Cap_Case: 0603; AEC Category: Q200; SizeArea_mm2: 1.28; SizeAreaWB_mm2: 4.68; SizeX_mm: 1.6; SizeY_mm: 0.8; SizeZ_mm: 1
D1-D4 = 1PS79SB70,115: Diode, Schottky, 70 V, 0.07 A, SOD-523; Manufacturer: NXP Semiconductor; U/M: EA; Vf_V: 0.41; Value: 70V; Value1: 0.07A; Value2: 0.41V; Io_A: 0.07; Vr_V: 70; TJmax_C: 150; SizeAreaWB_mm2: 5.13; SizeArea_mm2: 1.53; SizeX_mm: 1.7; SizeY_mm: 0.9; SizeZ_mm: 0.65; AEC Category: Q101
J1 J2 = SSW-110-23-F-D: Connector, Receptacle, 100mil, 10x2, Gold plated, TH; Manufacturer: Samtec; SymbolCreator: a0412235
J3 = OSTTC032162: Terminal Block, 3x1, 5.08 mm, Tin, TH; Manufacturer: On-Shore Technology; SymbolCreator: a0412235; Pitch_mm: 5.08; Gender: Female; Row_Count: 1; Current_A: 15; Voltage_V: 300; Cert_UL: Y
J4 = OSTTC022162: Terminal Block, 2-pole, 200mil, TH; Manufacturer: On-Shore Technology; SymbolCreator: a0412235; U/M: EA
R12-R20 = CRCW040220R0JNED: RES, 20, 5%, 0.063 W, 0402; Manufacturer: Vishay-Dale; CompType: Resistor; Value: 20; Value_Code: 20R0; Tolerance_%: 5; Power_W: 0.063; Value2: 0.063W; VDC_V: 50; TempCo: 200 ppm/C; EIA_Code: E24; U/M: EA; AEC Category: Q200; SizeArea_mm2: 0.5; SizeX_mm: 1; SizeZ_mm: 0.6
R21 R24-R38 = CRCW040210K0JNED: RES, 10 k, 5%, 0.063 W, 0402; Manufacturer: Vishay-Dale; CompType: Resistor; Value: 10k; Res_ohm: 10000; Value_Code: 10k0; Tolerance_%: 5; Power_W: 0.063; Value2: 0.063W; VDC_V: 50; TempCo: 200 ppm/C; SizeArea_mm2: 0.5; SizeX_mm: 1; SizeZ_mm: 0.6; EIA_Code: E24; U/M: EA; AEC Category: Q200
R22 R23 = CRCW04020000Z0ED: as R3 on sheet TIDA-00913_GAN
TP1 TP2 = 5001: Test Point, Miniature, Black, TH; Manufacturer: Keystone; CompType: Test Point Loop; ContactFinish: Silver
U4 = SN74AVC8T245RHLR: 8-BIT DUAL-SUPPLY BUS TRANSCEIVER WITH CONFIGURABLE VOLTAGE TRANSLATION AND 3-STATE OUTPUTS, RHL0024A; Manufacturer: Texas Instruments; SymbolCreator: Altium; CompType: IC; U/M: EA

## Sheet TIDA-00913_PS.SchDoc
size 431 x 279 mm; Date: Not shown in title block; ApprovedBy: Not shown in title block; CheckedBy: Not shown in title block; Author: Not shown in title block; CompanyName: Not shown in title block; Engineer: Not shown in title block; Organization: Not shown in title block; Address1: Not shown in title block; Address2: Not shown in title block; Address3: Not shown in title block; Address4: Not shown in title block; DocumentNumber: 1; Revision: Use project parameter SCH_Rev; SheetNumber: 2; SheetTotal: 3; PageSetup: Record=PageOptions¦CenterHorizontal=True¦CenterVertical=True¦PrintScale=1.00¦XCorrection=1.00¦YCorrection=1.00¦PrintKind=0¦BorderSize=5000000¦LeftOffset=0¦BottomOffset=0¦Orientation=2¦PaperLength=1000¦PaperWidth=1000¦Scale=100¦PaperSource=15¦PrintQuality=600¦MediaType=1¦DitherType=10¦PrintScaleMode=1¦PaperKind=Letter
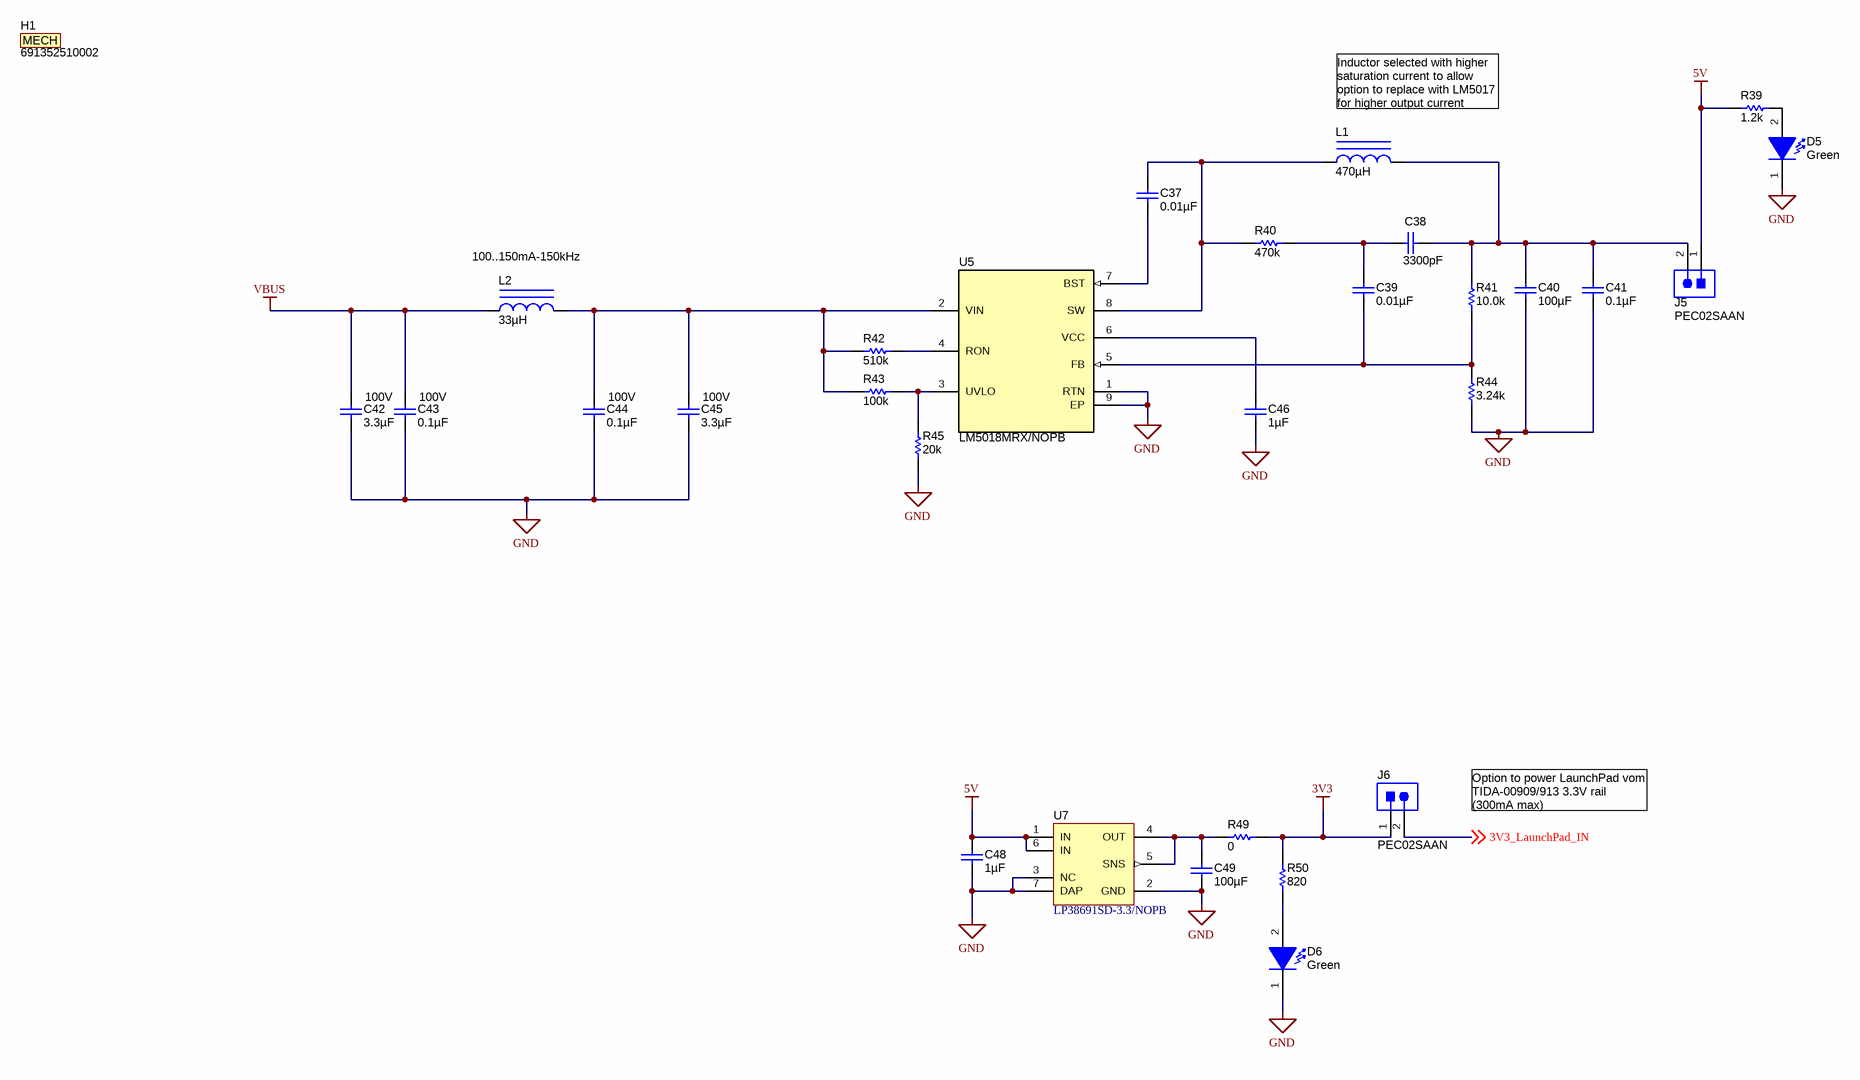
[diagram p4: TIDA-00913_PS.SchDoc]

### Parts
C37  ValueDisplayed: 0.01µF  [0402]  (hidden comment: GRM155R61C103KA01D)
C38  ValueDisplayed: 3300pF  [0603]  (hidden comment: GRM188R72A332KA01D)
C39  ValueDisplayed: 0.01µF  [0805_HV]  (hidden comment: GRM216R71H103KA01D)
C40  ValueDisplayed: 100µF  [1206_190]  (hidden comment: C3216X5R1A107M160AC)
C41  ValueDisplayed: 0.1µF  [0402]  (hidden comment: C1005X7R1E104M050BB)
C42  ValueDisplayed: 3.3µF  Value2: 100V  [1206_190]  (hidden comment: C3216X7S2A335M160AB)
C43  ValueDisplayed: 0.1µF  Value2: 100V  [0603]  (hidden comment: GRM188R72A104KA35D)
C44  ValueDisplayed: 0.1µF  Value2: 100V  [0603]  (hidden comment: GRM188R72A104KA35D)
C45  ValueDisplayed: 3.3µF  Value2: 100V  [1206_190]  (hidden comment: C3216X7S2A335M160AB)
C46  ValueDisplayed: 1µF  [0603S]  (hidden comment: GRM188R71A105KA61D)
C48  ValueDisplayed: 1µF  [0402_070]  (hidden comment: GCM155C71A105KE38D)
C49  ValueDisplayed: 100µF  [1206_180]  (hidden comment: GRM31CR60J107ME39L)
D5  value Green  [WL-SMCW_GREEN]  (hidden comment: 150060GS75000)
D6  value Green  [WL-SMCW_GREEN]  (hidden comment: 150060GS75000)
H1  691352510002  (mechanical)
J5  PEC02SAAN  [CONN_PEC02SAAN]
J6  PEC02SAAN  [CONN_PEC02SAAN]
L1  ValueDisplayed: 470µH  [WE-PD_1210]  (hidden comment: 7447709471)
L2  ValueDisplayed: 33µH  [NLCV25]  (hidden comment: NLFV25T-330K-PF)
R39  ValueDisplayed: 1.2k  [0402]  (hidden comment: CRCW04021K20JNED)
R40  ValueDisplayed: 470k  [0402]  (hidden comment: CRCW0402470KJNED)
R41  ValueDisplayed: 10.0k  [0402]  (hidden comment: CRCW040210K0FKED)
R42  ValueDisplayed: 510k  [0603S]  (hidden comment: RC0603FR-07510KL)
R43  ValueDisplayed: 100k  [0603]  (hidden comment: CRCW0603100KJNEA)
R44  ValueDisplayed: 3.24k  [0402]  (hidden comment: CRCW04023K24FKED)
R45  ValueDisplayed: 20k  [0402]  (hidden comment: CRCW040220K0JNED)
R49  ValueDisplayed: 0  [0402]  (hidden comment: CRCW04020000Z0ED)
R50  ValueDisplayed: 820  [0402]  (hidden comment: CRCW0402820RJNED)
U5  LM5018MRX/NOPB  [DDA0008B_N]
U7  LP38691SD-3.3/NOPB  [SDE06A_full]

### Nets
3V3: J6.1 R49.2 R50.2
5V: C48.1 J5.1 R39.2 U7.1(IN) U7.6(IN)
GND: C40.2 C41.2 C42.2 C43.2 C44.2 C45.2 C46.2 C48.2 C49.2 D5.1(K) D6.1(K) R44.1 R45.1 U5.1(RTN) U5.9(EP) U7.2(GND) U7.3(NC) U7.7(DAP)
VBUS: C42.1 C43.1 L2.1
3V3_LaunchPad_IN: J6.2 ; off-sheet 3V3_LaunchPad_IN
NetC37_1: C37.1 U5.7(BST)
NetC37_2: C37.2 L1.1 R40.1 U5.8(SW)
NetC38_1: C38.1 C40.1 C41.1 J5.2 L1.2 R41.2
NetC38_2: C38.2 C39.1 R40.2
NetC39_2: C39.2 R41.1 R44.2 U5.5(FB)
NetC44_1: C44.1 C45.1 L2.2 R42.1 R43.1 U5.2(VIN)
NetC46_1: C46.1 U5.6(VCC)
NetC49_1: C49.1 R49.1 U7.4(OUT) U7.5(SNS)
NetD5_2: D5.2(A) R39.1
NetD6_2: D6.2(A) R50.1
NetR42_2: R42.2 U5.4(RON)
NetR43_2: R43.2 R45.2 U5.3(UVLO)

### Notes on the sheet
- Inductor selected with higher saturation current to allow option to replace with LM5017 for higher output current
- (near L2) 100..150mA-150kHz
- Option to power LaunchPad vom TIDA-00909/913 3.3V rail (300mA max)

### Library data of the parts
C37 = GRM155R61C103KA01D: CAP, CERM, 0.01 µF, 16 V, +/- 10%, X5R, 0402; Manufacturer: MuRata; Polarized: N; CompType: Capacitor; Value: 0.01uF; U/M: EA; Cap_F: 0.00000001; Tolerance_%: 10; Value1: Unknown; VDC_V: 16; Value2: 16V; TaMin_C: -55; TaMax_C: 85; AEC Category: Q200; SizeArea_mm2: 0.5; SizeAreaWB_mm2: 3; SizeX_mm: 1; SizeZ_mm: 0.6
C38 = GRM188R72A332KA01D: CAP, CERM, 3300 pF, 100 V, +/- 10%, X7R, 0603; Manufacturer: MuRata; Polarized: N; CompType: Capacitor; Value: 3300pF; U/M: EA; Cap_F: 0.0000000033; Tolerance_%: 10; Value1: Unknown; VDC_V: 100; Value2: 100V; TaMin_C: -55; TaMax_C: 125; AEC Category: Q200
C39 = GRM216R71H103KA01D: CAP, CERM, 0.01 µF, 50 V, +/- 10%, X7R, 0805; Manufacturer: MuRata; Polarized: N; CompType: Capacitor; Value: 0.01uF; U/M: EA; Cap_F: 0.00000001; Tolerance_%: 10; Value1: Unknown; VDC_V: 50; Value2: 50V; TaMin_C: -55; TaMax_C: 125; Cap_Case: 0805; AEC Category: Q200; SizeArea_mm2: 2.5; SizeAreaWB_mm2: 6.75; SizeX_mm: 2; SizeY_mm: 1.25; SizeZ_mm: 1.45
C40 = C3216X5R1A107M160AC: CAP, CERM, 100 µF, 10 V, +/- 20%, X5R, 1206_190; Manufacturer: TDK; Polarized: N; CompType: Capacitor; Value: 100uF; U/M: EA; Cap_F: 0.0001; Tolerance_%: 20; ESR_ohm: 0.002838; Value1: 0.002838 ohm; VDC_V: 10; Value2: 10V; IRMS_A: 4.30694; TaMin_C: -55; TaMax_C: 85; AEC Category: Q200; SizeArea_mm2: 5.12; SizeAreaWB_mm2: 10.92; SizeX_mm: 3.2; SizeY_mm: 1.6; SizeZ_mm: 1.9
C41 = C1005X7R1E104M050BB: CAP, CERM, 0.1 µF, 25 V, +/- 20%, X7R, 0402; Manufacturer: TDK; Polarized: N; CompType: Capacitor; Value: 0.1uF; U/M: EA; Cap_F: 0.0000001; Tolerance_%: 20; Value1: Unknown; VDC_V: 25; Value2: 25V; TaMin_C: -55; TaMax_C: 125; AEC Category: Q200
C42 = C3216X7S2A335M160AB: CAP, CERM, 3.3 µF, 100 V, +/- 20%, X7S, 1206_190; Manufacturer: TDK; Polarized: N; CompType: Capacitor; Value: 3.3uF; U/M: EA; Cap_F: 0.0000033; Tolerance_%: 20; ESR_ohm: 0.003048; Value1: 0.003048 ohm; VDC_V: 100; IRMS_A: 4.15703; TaMin_C: -55; TaMax_C: 125; SizeArea_mm2: 5.12; SizeAreaWB_mm2: 10.92; SizeX_mm: 3.2; SizeY_mm: 1.6; SizeZ_mm: 1.9; AEC Category: Q200
C43 C44 = GRM188R72A104KA35D: CAP, CERM, 0.1 µF, 100 V, +/- 10%, X7R, 0603; Manufacturer: MuRata; Polarized: N; CompType: Capacitor; Value: 0.1uF; U/M: EA; Cap_F: 0.0000001; Tolerance_%: 10; Value1: Unknown; VDC_V: 100; TaMin_C: -55; TaMax_C: 125; SizeArea_mm2: 1.28; SizeAreaWB_mm2: 4.68; SizeX_mm: 1.6; SizeY_mm: 0.8; SizeZ_mm: 1; AEC Category: Q200
C45 = C3216X7S2A335M160AB: as C2 on sheet TIDA-00913_GAN
C46 = GRM188R71A105KA61D: CAP, CERM, 1 µF, 10 V, +/- 10%, X7R, 0603; Manufacturer: MuRata; Polarized: N; CompType: Capacitor; Value: 1uF; U/M: EA; Cap_F: 0.000001; Tolerance_%: 10; ESR_ohm: 0.011; Value1: 0.011 ohm; Value2: 10V; TaMin_C: -55; TaMax_C: 125; Cap_Case: 0603; SizeArea_mm2: 1.28; SizeAreaWB_mm2: 4.68; SizeX_mm: 1.6; SizeY_mm: 0.8; SizeZ_mm: 1; AEC Category: Q200
C48 = GCM155C71A105KE38D: CAP, CERM, 1 µF, 10 V, +/- 10%, X7S, AEC-Q200 Grade 1, 0402; Manufacturer: MuRata; Polarized: N; CompType: Capacitor; Value: 1uF; U/M: EA; Cap_F: 0.000001; Tolerance_%: 10; Value1: Unknown; Value2: 10V; TaMin_C: -55; TaMax_C: 125; Cap_Case: 0402; SizeArea_mm2: 0.5; SizeAreaWB_mm2: 3; SizeX_mm: 1; SizeZ_mm: 0.7; AEC Category: Q200; AEC Qualified: Y
C49 = GRM31CR60J107ME39L: CAP, CERM, 100 µF, 6.3 V, +/- 20%, X5R, 1206; Manufacturer: MuRata; Polarized: N; CompType: Capacitor; Value: 100uF; U/M: EA; Cap_F: 0.0001; Tolerance_%: 20; ESR_ohm: 0.003; Value1: 0.003 ohm; VDC_V: 6.3; Value2: 6.3V; TaMin_C: -55; TaMax_C: 85; Cap_Case: 1206; AEC Category: Q200; SizeArea_mm2: 5.12; SizeAreaWB_mm2: 10.92; SizeX_mm: 3.2; SizeY_mm: 1.6; SizeZ_mm: 1.8
D5 D6 = 150060GS75000: LED, Green, SMD; Manufacturer: Wurth Elektronik; Type: InGaN; Vf_V: 3.2; Value2: 3.2V; Io_A: 0.02; Tjmax_C: 85; Value1: W; Angle: 140; U/M: EA
H1 = 691352510002: TERM BLOCK PLUG 2POS 5.08MM; Manufacturer: Wurth Elektronik; SymbolCreator: codlsc
J5 J6 = PEC02SAAN: Header, 100mil, 2x1, Tin, TH; Manufacturer: Sullins Connector Solutions; SymbolCreator: a0412235; Pitch_mm: 2.54; Gender: Male; Shrouded: N; Row_Count: 1; Current_A: 3; Voltage_V: 1800; Cert_UL: Y
L1 = 7447709471: Inductor, Shielded Drum Core, Ferrite, 470 µH, 1.4 A, 0.56 ohm, SMD; Manufacturer: Wurth Elektronik; Value: 470uH; Ind_H: 470.0E-6; Imax_A: 1.4; Irms: 1.4A @ 40C rise; Isat: 1.5A @ 10% inductance drop; DCR_ohm: 0.56; Value2: 1.4A; AEC Category: Q200
L2 = NLFV25T-330K-PF: Inductor, Shielded, Ferrite, 33 µH, 0.085 A, 1.4 ohm, SMD; Manufacturer: TDK; Value: 33uH; Ind_H: 33.0E-6; Imax_A: 0.085; Irms: 0.085A @ 20C rise; Isat: 0.085A @ 10% inductance drop; DCR_ohm: 1.4; Value1: 1.4 ohm; Value2: 0.085A; AEC Category: Q200
R39 = CRCW04021K20JNED: RES, 1.2 k, 5%, 0.063 W, 0402; Manufacturer: Vishay-Dale; CompType: Resistor; Value: 1.2k; Res_ohm: 1200; Value_Code: 1k20; Tolerance_%: 5; Power_W: 0.063; Value2: 0.063W; VDC_V: 50; TempCo: 200 ppm/C; EIA_Code: E24; U/M: EA; AEC Category: Q200; SizeArea_mm2: 0.5; SizeX_mm: 1; SizeZ_mm: 0.6
R40 = CRCW0402470KJNED: RES, 470 k, 5%, 0.063 W, 0402; Manufacturer: Vishay-Dale; CompType: Resistor; Value: 470k; Res_ohm: 470000; Tolerance_%: 5; Power_W: 0.063; Value2: 0.063W; VDC_V: 50; TempCo: 200 ppm/C; EIA_Code: E24; U/M: EA; AEC Category: Q200; SizeArea_mm2: 0.5; SizeX_mm: 1; SizeZ_mm: 0.6
R41 = CRCW040210K0FKED: as R48 on sheet TIDA-00913_GAN
R42 = RC0603FR-07510KL: RES, 510 k, 1%, 0.1 W, 0603; Manufacturer: Yageo America; CompType: Resistor; Value: 510k; Res_ohm: 510000; Tolerance_%: 1; Power_W: 0.1; Value2: 0.1W; VDC_V: 150; TempCo: 200 ppm/C; SizeArea_mm2: 1.28; SizeX_mm: 1.6; SizeY_mm: 0.8; U/M: EA; AEC Category: Q200
R43 = CRCW0603100KJNEA: RES, 100 k, 5%, 0.1 W, 0603; Manufacturer: Vishay-Dale; CompType: Resistor; Value: 100k; Res_ohm: 100000; Tolerance_%: 5; Power_W: 0.1; Value2: 0.1W; VDC_V: 75; TempCo: 200 ppm/C; SizeArea_mm2: 1.28; SizeX_mm: 1.6; SizeY_mm: 0.8; SizeZ_mm: 1; EIA_Code: E24; U/M: EA; AEC Category: Q200
R44 = CRCW04023K24FKED: RES, 3.24 k, 1%, 0.063 W, 0402; Manufacturer: Vishay-Dale; CompType: Resistor; Value: 3.24k; Res_ohm: 3240; Value_Code: 3k24; Tolerance_%: 1; Power_W: 0.063; Value2: 0.063W; VDC_V: 50; TempCo: 100 ppm/C; SizeArea_mm2: 0.5; SizeZ_mm: 0.6; EIA_Code: E96; U/M: EA; AEC Category: Q200
R45 = CRCW040220K0JNED: RES, 20 k, 5%, 0.063 W, 0402; Manufacturer: Vishay-Dale; CompType: Resistor; Value: 20k; Res_ohm: 20000; Value_Code: 20k0; Tolerance_%: 5; Power_W: 0.063; Value2: 0.063W; VDC_V: 50; TempCo: 200 ppm/C; SizeArea_mm2: 0.5; SizeX_mm: 1; SizeZ_mm: 0.6; EIA_Code: E24; U/M: EA; AEC Category: Q200
R49 = CRCW04020000Z0ED: RES, 0, 5%, 0.063 W, 0402; Manufacturer: Vishay-Dale; CompType: Resistor; Value: 0; Value_Code: 0000; Tolerance_%: 5; Power_W: 0.063; Value2: 0.063W; VDC_V: 50; TempCo: 200 ppm/C; EIA_Code: E24; U/M: EA
R50 = CRCW0402820RJNED: RES, 820, 5%, 0.063 W, 0402; Manufacturer: Vishay-Dale; CompType: Resistor; Value: 820; Value_Code: 820R; Tolerance_%: 5; Power_W: 0.063; Value2: 0.063W; VDC_V: 50; TempCo: 200 ppm/C; EIA_Code: E24; U/M: EA; AEC Category: Q200
U5 = LM5018MRX/NOPB: 100V, 300mA Constant On-Time Synchronous Buck Regulator, DDA0008B; Alternate PartNumber: LM5018MR/NOPB; Manufacturer: Texas Instruments; SymbolCreator: a0412235; CompType: IC; U/M: EA; SizeArea_mm2: 31; SizeAreaWB_mm2: 57.4; SizeX_mm: 5; SizeY_mm: 6.2; SizeZ_mm: 1.7
U7 = LP38691SD-3.3/NOPB: 500mA Low Dropout CMOS Linear Regulators Stable with Ceramic Output Capacitors, 6-pin LLP, Pb-Free; Manufacturer: Texas Instruments; PackageTopMarking: ZXYTT*L120B; PowerWise: Y; CompType: LDO IC

## Sheet TIDA-00913_Sensing.SchDoc
size 431 x 279 mm; Date: Not shown in title block; ApprovedBy: Not shown in title block; CheckedBy: Not shown in title block; Author: Not shown in title block; CompanyName: Not shown in title block; Engineer: Not shown in title block; Organization: Not shown in title block; Address1: Not shown in title block; Address2: Not shown in title block; Address3: Not shown in title block; Address4: Not shown in title block; DocumentNumber: 1; Revision: Use project parameter SCH_Rev; SheetNumber: 2; SheetTotal: 3; PageSetup: Record=PageOptions¦CenterHorizontal=True¦CenterVertical=True¦PrintScale=1.00¦XCorrection=1.00¦YCorrection=1.00¦PrintKind=0¦BorderSize=5000000¦LeftOffset=0¦BottomOffset=0¦Orientation=2¦PaperLength=1000¦PaperWidth=1000¦Scale=100¦PaperSource=15¦PrintQuality=600¦MediaType=1¦DitherType=10¦PaperKind=Letter¦PrintScaleMode=1
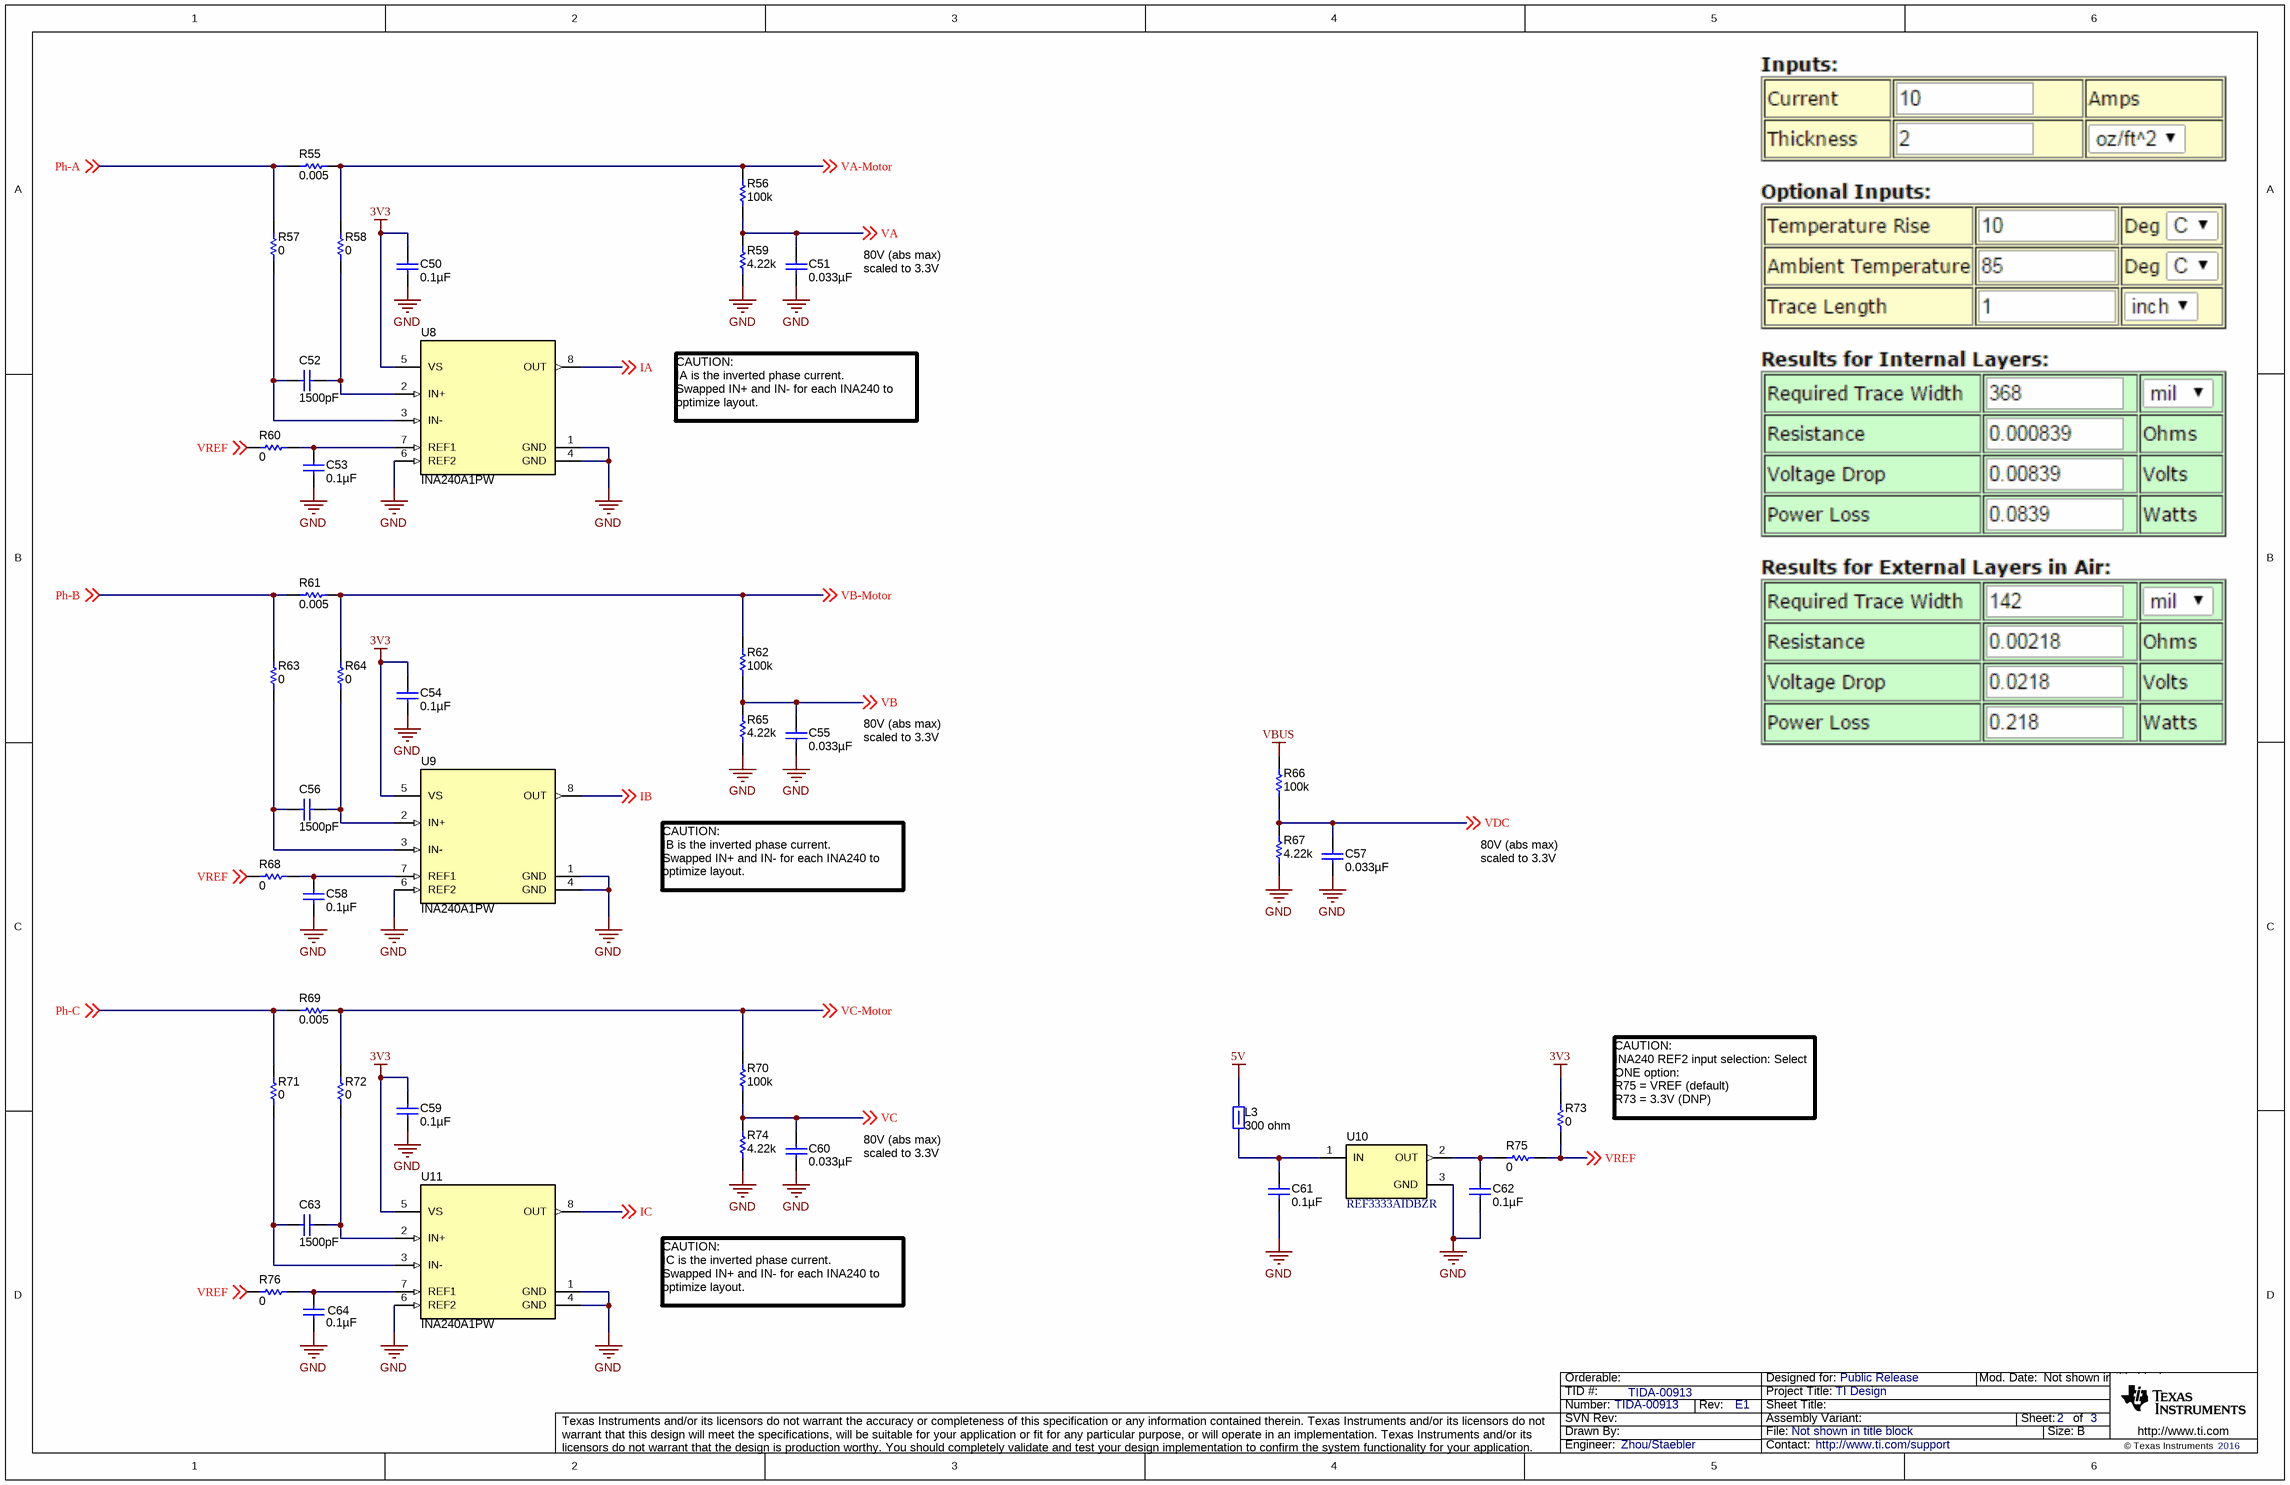
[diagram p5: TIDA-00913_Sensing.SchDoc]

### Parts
C50  ValueDisplayed: 0.1µF  [0402]  (hidden comment: GCM155R71C104KA55D)
C51  ValueDisplayed: 0.033µF  [0402]  (hidden comment: GRM155R71A333KA01D)
C52  ValueDisplayed: 1500pF  [0402]  (hidden comment: C0402H152J3GAC7867)
C53  ValueDisplayed: 0.1µF  [0603]  (hidden comment: GRM188R71C104KA01D)
C54  ValueDisplayed: 0.1µF  [0402]  (hidden comment: GCM155R71C104KA55D)
C55  ValueDisplayed: 0.033µF  [0402]  (hidden comment: GRM155R71A333KA01D)
C56  ValueDisplayed: 1500pF  [0402]  (hidden comment: C0402H152J3GAC7867)
C57  ValueDisplayed: 0.033µF  [0402]  (hidden comment: GRM155R71A333KA01D)
C58  ValueDisplayed: 0.1µF  [0603]  (hidden comment: GRM188R71C104KA01D)
C59  ValueDisplayed: 0.1µF  [0402]  (hidden comment: GCM155R71C104KA55D)
C60  ValueDisplayed: 0.033µF  [0402]  (hidden comment: GRM155R71A333KA01D)
C61  ValueDisplayed: 0.1µF  [0603]  (hidden comment: GRM188R71C104KA01D)
C62  ValueDisplayed: 0.1µF  [0603]  (hidden comment: GRM188R71C104KA01D)
C63  ValueDisplayed: 1500pF  [0402]  (hidden comment: C0402H152J3GAC7867)
C64  ValueDisplayed: 0.1µF  [0603]  (hidden comment: GRM188R71C104KA01D)
L3  value 300 ohm  [0402]  (hidden comment: 74279272)
R55  ValueDisplayed: 0.005  [CRE2512-R5_R9]  (hidden comment: CRE2512-FZ-R005E-3)
R56  ValueDisplayed: 100k  [0402]  (hidden comment: CRCW0402100KFKED)
R57  ValueDisplayed: 0  [0402]  (hidden comment: CRCW04020000Z0ED)
R58  ValueDisplayed: 0  [0402]  (hidden comment: CRCW04020000Z0ED)
R59  ValueDisplayed: 4.22k  [0402]  (hidden comment: CRCW04024K22FKED)
R60  ValueDisplayed: 0  [0402]  (hidden comment: CRCW04020000Z0ED)
R61  ValueDisplayed: 0.005  [CRE2512-R5_R9]  (hidden comment: CRE2512-FZ-R005E-3)
R62  ValueDisplayed: 100k  [0402]  (hidden comment: CRCW0402100KFKED)
R63  ValueDisplayed: 0  [0402]  (hidden comment: CRCW04020000Z0ED)
R64  ValueDisplayed: 0  [0402]  (hidden comment: CRCW04020000Z0ED)
R65  ValueDisplayed: 4.22k  [0402]  (hidden comment: CRCW04024K22FKED)
R66  ValueDisplayed: 100k  [0402]  (hidden comment: CRCW0402100KFKED)
R67  ValueDisplayed: 4.22k  [0402]  (hidden comment: CRCW04024K22FKED)
R68  ValueDisplayed: 0  [0402]  (hidden comment: CRCW04020000Z0ED)
R69  ValueDisplayed: 0.005  [CRE2512-R5_R9]  (hidden comment: CRE2512-FZ-R005E-3)
R70  ValueDisplayed: 100k  [0402]  (hidden comment: CRCW0402100KFKED)
R71  ValueDisplayed: 0  [0402]  (hidden comment: CRCW04020000Z0ED)
R72  ValueDisplayed: 0  [0402]  (hidden comment: CRCW04020000Z0ED)
R73  ValueDisplayed: 0  [0402]  (hidden comment: CRCW04020000Z0ED)
R74  ValueDisplayed: 4.22k  [0402]  (hidden comment: CRCW04024K22FKED)
R75  ValueDisplayed: 0  [0402]  (hidden comment: CRCW04020000Z0ED)
R76  ValueDisplayed: 0  [0402]  (hidden comment: CRCW04020000Z0ED)
U8  INA240A1PW  [PW0008A_N]
U9  INA240A1PW  [PW0008A_N]
U10  REF3333AIDBZR  [DBZ0003A_N]
U11  INA240A1PW  [PW0008A_N]

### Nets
3V3: C50.2 C54.2 C59.2 R73.2 U8.5(VS) U9.5(VS) U11.5(VS)
5V: L3.2
GND: C50.1 C51.2 C53.1 C54.1 C55.2 C57.2 C58.1 C59.1 C60.2 C61.1 C62.1 C64.1 R59.1 R65.1 R67.1 R74.1 U8.1(GND) U8.4(GND) U8.6(REF2) U9.1(GND) U9.4(GND) U9.6(REF2) U10.3(GND) U11.1(GND) U11.4(GND) U11.6(REF2)
VBUS: R66.2
IA: U8.8(OUT) ; off-sheet IA
IB: U9.8(OUT) ; off-sheet IB
IC: U11.8(OUT) ; off-sheet IC
Ph-A: R55.1 R57.2 ; off-sheet Ph-A
Ph-B: R61.1 R63.2 ; off-sheet Ph-B
Ph-C: R69.1 R71.2 ; off-sheet Ph-C
VA: C51.1 R56.1 R59.2 ; off-sheet VA
VA-MOTOR: R55.2 R56.2 R58.2 ; off-sheet VA-Motor
VB: C55.1 R62.1 R65.2 ; off-sheet VB
VB-MOTOR: R61.2 R62.2 R64.2 ; off-sheet VB-Motor
VC: C60.1 R70.1 R74.2 ; off-sheet VC
VC-MOTOR: R69.2 R70.2 R72.2 ; off-sheet VC-Motor
VDC: C57.1 R66.1 R67.2 ; off-sheet VDC
VREF: R60.1 R68.1 R73.1 R75.2 R76.1 ; off-sheet VREF
NetC52_1: C52.1 R57.1 U8.3(IN-)
NetC52_2: C52.2 R58.1 U8.2(IN+)
NetC53_2: C53.2 R60.2 U8.7(REF1)
NetC56_1: C56.1 R63.1 U9.3(IN-)
NetC56_2: C56.2 R64.1 U9.2(IN+)
NetC58_2: C58.2 R68.2 U9.7(REF1)
NetC61_2: C61.2 L3.1 U10.1(IN)
NetC62_2: C62.2 R75.1 U10.2(OUT)
NetC63_1: C63.1 R71.1 U11.3(IN-)
NetC63_2: C63.2 R72.1 U11.2(IN+)
NetC64_2: C64.2 R76.2 U11.7(REF1)

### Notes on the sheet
- 80V (abs max) scaled to 3.3V
- CAUTION:
  IA is the inverted phase current.
  Swapped IN+ and IN- for each INA240 to optimize layout.
- CAUTION:
  IB is the inverted phase current.
  Swapped IN+ and IN- for each INA240 to optimize layout.
- CAUTION:
  INA240 REF2 input selection: Select ONE option:
  R75 = VREF (default)
  R73 = 3.3V (DNP)
- CAUTION:
  IC is the inverted phase current.
  Swapped IN+ and IN- for each INA240 to optimize layout.

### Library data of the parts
C50 C54 C59 = GCM155R71C104KA55D: as C13 on sheet TIDA-00913_GAN
C51 C55 C57 C60 = GRM155R71A333KA01D: CAP, CERM, 0.033 µF, 10 V, +/- 10%, X7R, 0402; Manufacturer: MuRata; Polarized: N; CompType: Capacitor; Value: 0.033uF; U/M: EA; Cap_F: 0.000000033; Tolerance_%: 10; Value1: Unknown; Value2: 10V; TaMin_C: -55; TaMax_C: 125; AEC Category: Q200; SizeArea_mm2: 0.5; SizeAreaWB_mm2: 3; SizeX_mm: 1; SizeZ_mm: 0.6
C52 C56 C63 = C0402H152J3GAC7867: CAP, CERM, 1500 pF, 25 V, +/- 5%, C0G/NP0, 0402; Manufacturer: Kemet; Polarized: N; CompType: Capacitor; Value: 1500pF; U/M: EA; Cap_F: 0.0000000015; Tolerance_%: 5; Value1: Unknown; VDC_V: 25; Value2: 25V; TaMin_C: -55; TaMax_C: 200; AEC Category: Q200; SizeArea_mm2: 0.5; SizeAreaWB_mm2: 3; SizeX_mm: 1; SizeZ_mm: 0.6
C53 C58 C61 C62 C64 = GRM188R71C104KA01D: CAP, CERM, 0.1 µF, 16 V, +/- 10%, X7R, 0603; Manufacturer: MuRata; Polarized: N; CompType: Capacitor; Value: 0.1uF; U/M: EA; Cap_F: 0.0000001; Tolerance_%: 10; Value1: Unknown; VDC_V: 16; Value2: 16V; TaMin_C: -55; TaMax_C: 125
L3 = 74279272: Ferrite Bead, 300 ohm @ 100 MHz, 0.2 A, 0402; Manufacturer: Wurth Elektronik; Imax_A: 0.2; DCR_ohm: 0.8; Value1: 0.8 ohm; Value2: 0.2A; ZTyp@100MHz_Ohm: 300
R55 R61 R69 = CRE2512-FZ-R005E-3: RES, 0.005, 1%, 3 W, AEC-Q200 Grade 0, 2512; Manufacturer: Bourns; CompType: Resistor; Value: 0.005; Value_Code: 5L000; Tolerance_%: 1; Power_W: 3; Value2: 3W; TempCo: 75 ppm/C; EIA_Code: E96; U/M: EA; AEC Category: Q200; AEC Qualified: Y; AEC Grade: 0; SizeArea_mm2: 21.6075; SizeX_mm: 6.45; SizeY_mm: 3.35; SizeZ_mm: 0.9
R56 R62 R66 R70 = CRCW0402100KFKED: RES, 100 k, 1%, 0.063 W, 0402; Manufacturer: Vishay-Dale; CompType: Resistor; Value: 100k; Res_ohm: 100000; Tolerance_%: 1; Power_W: 0.063; Value2: 0.063W; VDC_V: 50; TempCo: 100 ppm/C; EIA_Code: E96; U/M: EA; AEC Category: Q200; SizeArea_mm2: 0.5; SizeZ_mm: 0.6
R57 R58 R63 R64 R71 R72 = CRCW04020000Z0ED: as R3 on sheet TIDA-00913_GAN
R59 R65 R67 R74 = CRCW04024K22FKED: RES, 4.22 k, 1%, 0.063 W, 0402; Manufacturer: Vishay-Dale; CompType: Resistor; Value: 4.22k; Res_ohm: 4220; Value_Code: 4k22; Tolerance_%: 1; Power_W: 0.063; Value2: 0.063W; VDC_V: 50; TempCo: 100 ppm/C; EIA_Code: E96; U/M: EA; AEC Category: Q200; SizeArea_mm2: 0.5; SizeZ_mm: 0.6
R60 R68 R73 R75 R76 = CRCW04020000Z0ED: as R49 on sheet TIDA-00913_PS
U8 U9 U11 = INA240A1PW: Wide Common-Mode Range, Voltage Output, High or Low-Side Bi-Directional Zero-Drift Current Shunt Monitor, PW0008A; Manufacturer: Texas Instruments; SymbolCreator: Altium; CompType: IC; U/M: EA
U10 = REF3333AIDBZR: 30 ppm / degC Drift, 3.9 uA Voltage Reference, -40 to 125 degC, 3-pin SOT-23 (DBZ), Green (RoHS & no Sb/Br); Manufacturer: Texas Instruments; Alternate PartNumber: Equivalent; Initial Accuracy @ 25/deg C(%): 0.15; Iout/Iz(Max)(mA): 5; Rating: Catalog; SubFamily: Series Voltage Reference; Temp Coeff(Max)(ppm/ degree C): 30; Temp Coeff(Typ)(ppm/ degree C): 8; VI(Max)(V): 5.5; VI(Min)(V): 3.5; VO(V): 3.3

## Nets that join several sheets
3V3: TIDA-00913_GAN (5 pins), TIDA-00913_Interface (9 pins), TIDA-00913_PS (J6.1 R49.2 R50.2), TIDA-00913_Sensing (7 pins)
5V: TIDA-00913_GAN (R3.2 R4.2 R9.2), TIDA-00913_Interface (R23.2), TIDA-00913_PS (5 pins), TIDA-00913_Sensing (L3.2)
GND: TIDA-00913_GAN (16 pins), TIDA-00913_Interface (30 pins), TIDA-00913_PS (18 pins), TIDA-00913_Sensing (26 pins)
PGND: TIDA-00913_GAN (21 pins), TIDA-00913_Interface (J4.2 TP2.1)
VBUS: TIDA-00913_GAN (17 pins), TIDA-00913_Interface (J4.1), TIDA-00913_PS (C42.1 C43.1 L2.1), TIDA-00913_Sensing (R66.2)
3V3_LaunchPad_IN: TIDA-00913_Interface (J1.1), TIDA-00913_PS (J6.2)
IA: TIDA-00913_Interface (R16.1), TIDA-00913_Sensing (U8.8)
IB: TIDA-00913_Interface (R18.1), TIDA-00913_Sensing (U9.8)
IC: TIDA-00913_Interface (R19.1), TIDA-00913_Sensing (U11.8)
OT: TIDA-00913_GAN (R48.1 U6.3), TIDA-00913_Interface (J2.13)
Ph-A: TIDA-00913_GAN (U1.8), TIDA-00913_Sensing (R55.1 R57.2)
Ph-B: TIDA-00913_GAN (U2.8), TIDA-00913_Sensing (R61.1 R63.2)
Ph-C: TIDA-00913_GAN (U3.8), TIDA-00913_Sensing (R69.1 R71.2)
PWM_AH: TIDA-00913_GAN (R5.2), TIDA-00913_Interface (R31.2 U4.21)
PWM_AL: TIDA-00913_GAN (R6.2), TIDA-00913_Interface (R32.2 U4.20)
PWM_BH: TIDA-00913_GAN (R7.2), TIDA-00913_Interface (R33.2 U4.19)
PWM_BL: TIDA-00913_GAN (R8.2), TIDA-00913_Interface (R34.2 U4.18)
PWM_CH: TIDA-00913_GAN (R10.2), TIDA-00913_Interface (R35.2 U4.17)
PWM_CL: TIDA-00913_GAN (R11.2), TIDA-00913_Interface (R36.2 U4.16)
VA: TIDA-00913_Interface (R13.1), TIDA-00913_Sensing (C51.1 R56.1 R59.2)
VA-MOTOR: TIDA-00913_Interface (J3.3), TIDA-00913_Sensing (R55.2 R56.2 R58.2)
VB: TIDA-00913_Interface (R14.1), TIDA-00913_Sensing (C55.1 R62.1 R65.2)
VB-MOTOR: TIDA-00913_Interface (J3.2), TIDA-00913_Sensing (R61.2 R62.2 R64.2)
VC: TIDA-00913_Interface (R15.1), TIDA-00913_Sensing (C60.1 R70.1 R74.2)
VC-MOTOR: TIDA-00913_Interface (J3.1), TIDA-00913_Sensing (R69.2 R70.2 R72.2)
VDC: TIDA-00913_Interface (R12.1), TIDA-00913_Sensing (C57.1 R66.1 R67.2)
VREF: TIDA-00913_Interface (R20.1), TIDA-00913_Sensing (5 pins)

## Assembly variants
001: not fitted C52 C56 C63 FID1 FID2 FID3 R23 R51 R52 R53 R73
